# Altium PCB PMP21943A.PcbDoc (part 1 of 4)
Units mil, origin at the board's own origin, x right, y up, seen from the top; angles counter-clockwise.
Board outline 5100 x 3900 mil, 8 copper layers (Top Layer, Signal Layer 1, Signal Layer 2, Signal Layer 3, Signal Layer 4, Signal Layer 5, Signal Layer 6, Bottom Layer), stack 61.6 mil thick; 371 components, 163 nets, 967 pads, 1147 vias.
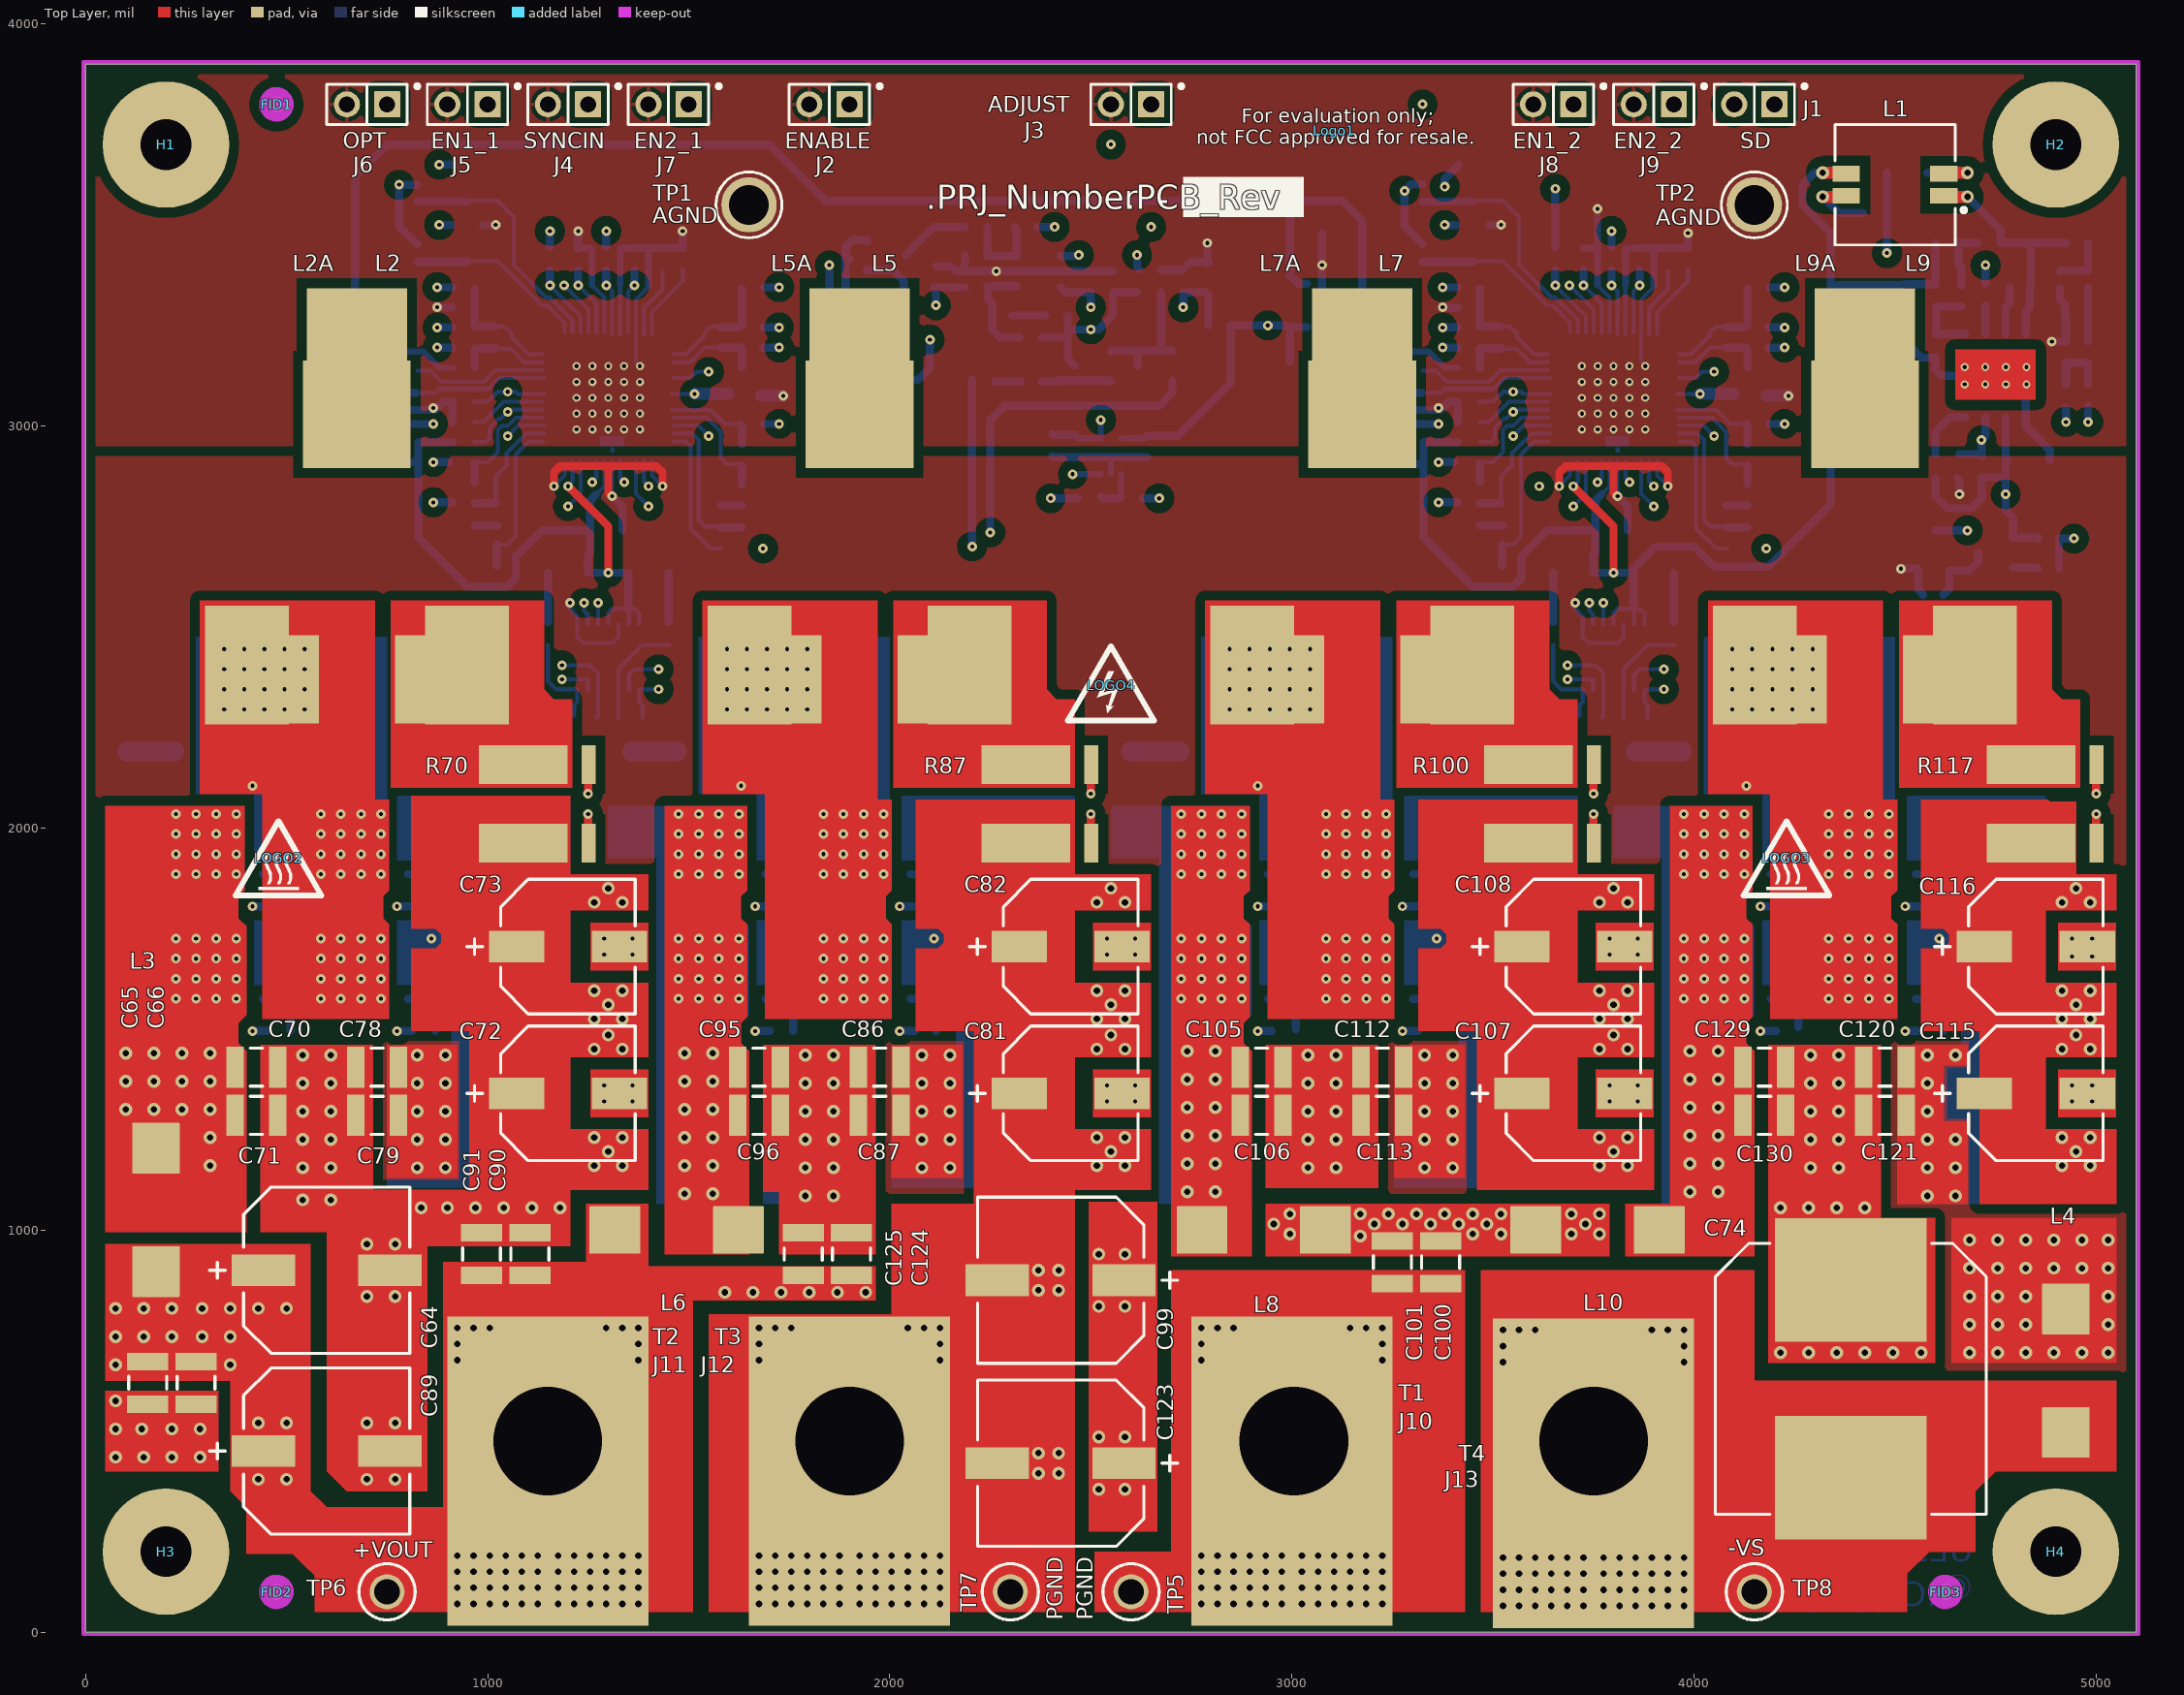
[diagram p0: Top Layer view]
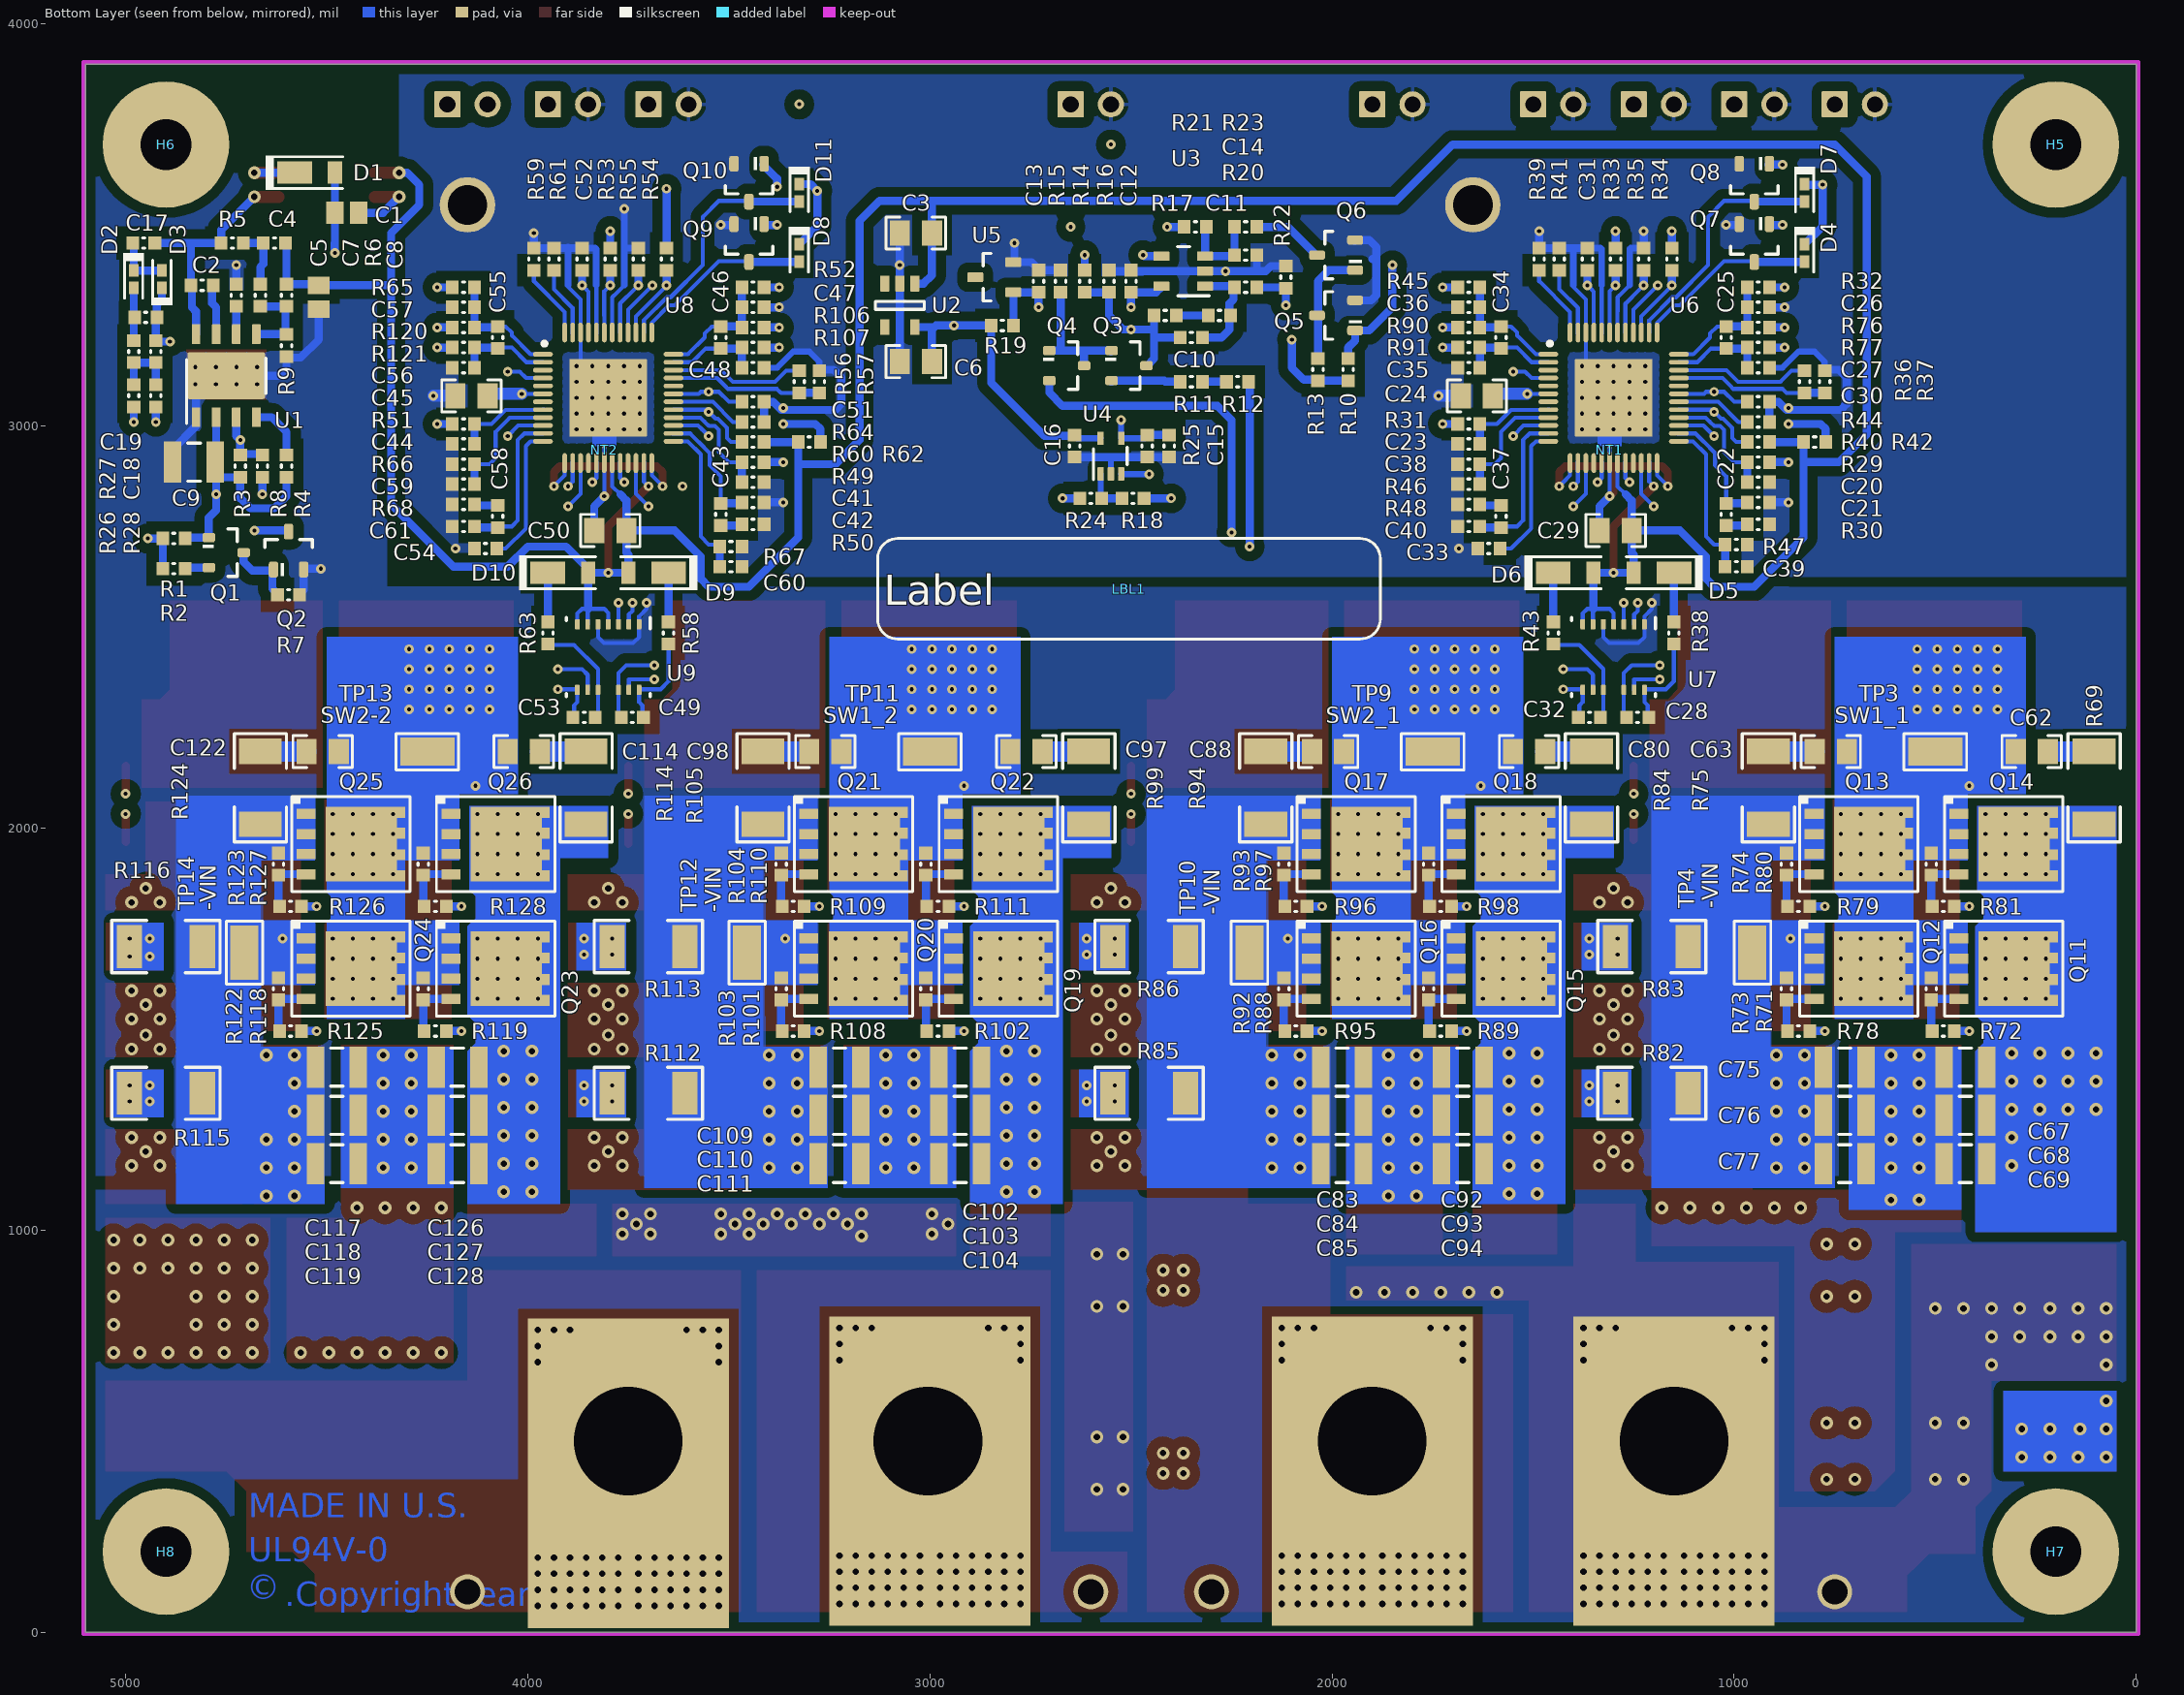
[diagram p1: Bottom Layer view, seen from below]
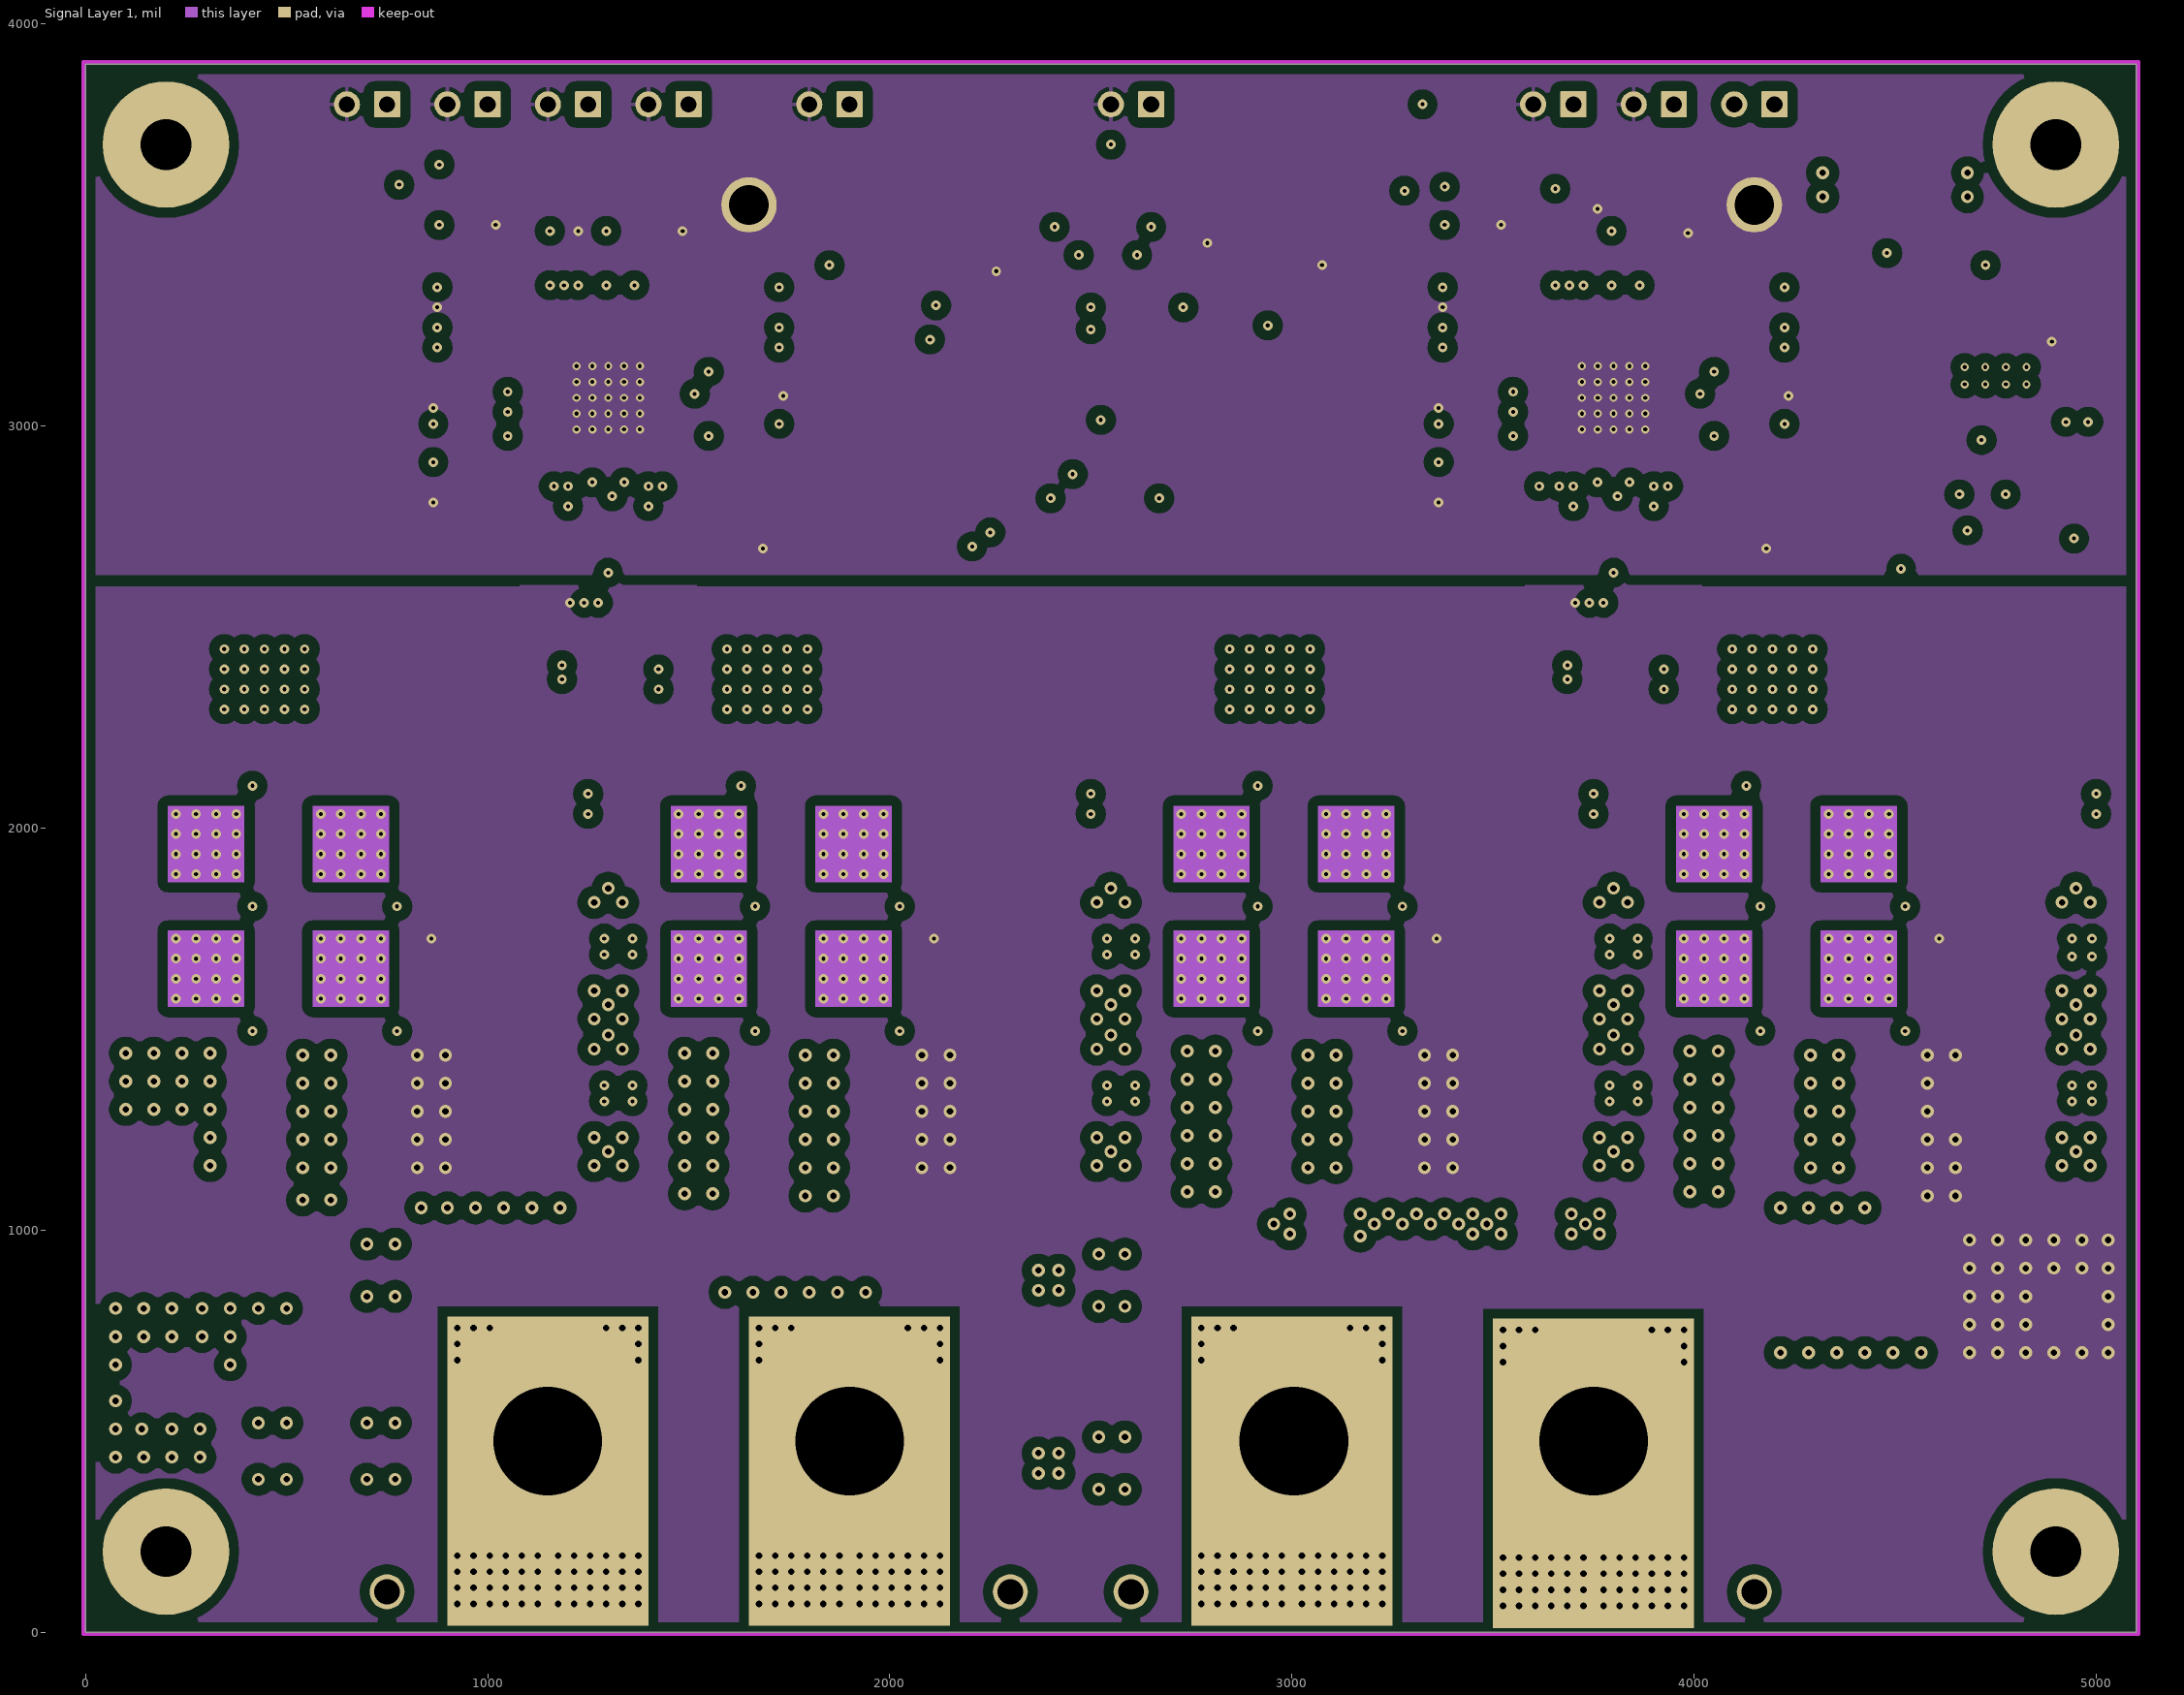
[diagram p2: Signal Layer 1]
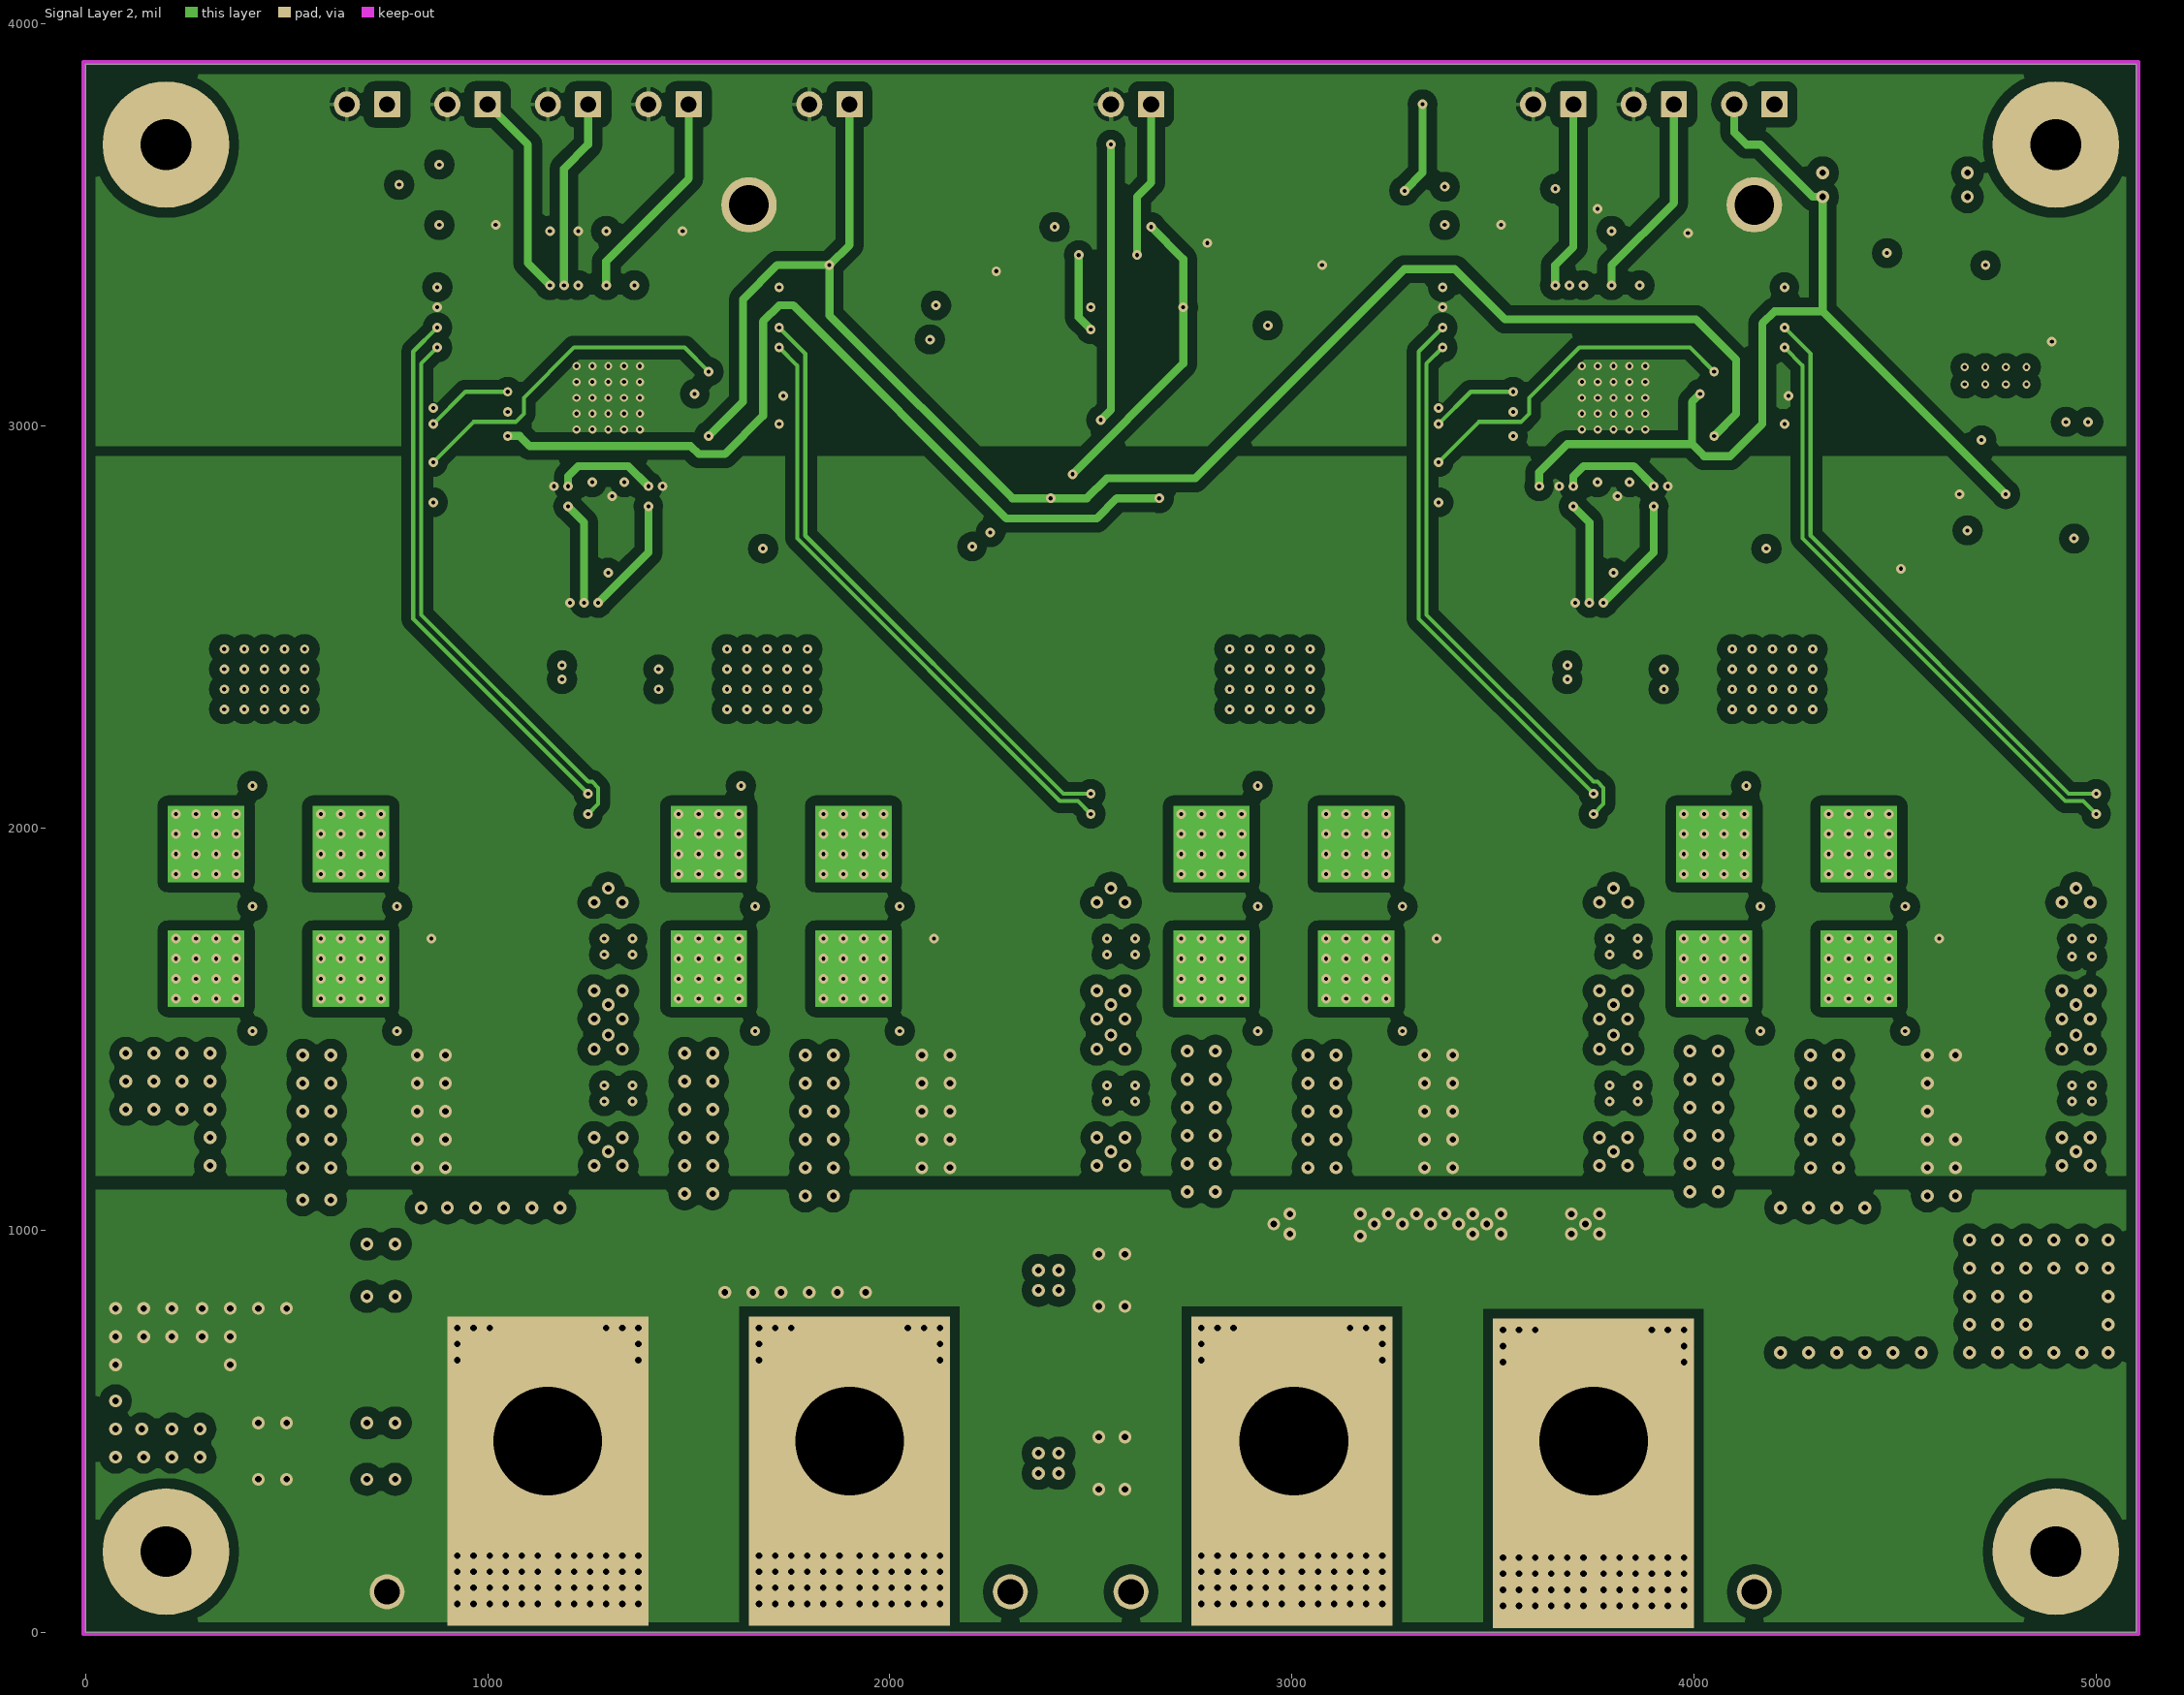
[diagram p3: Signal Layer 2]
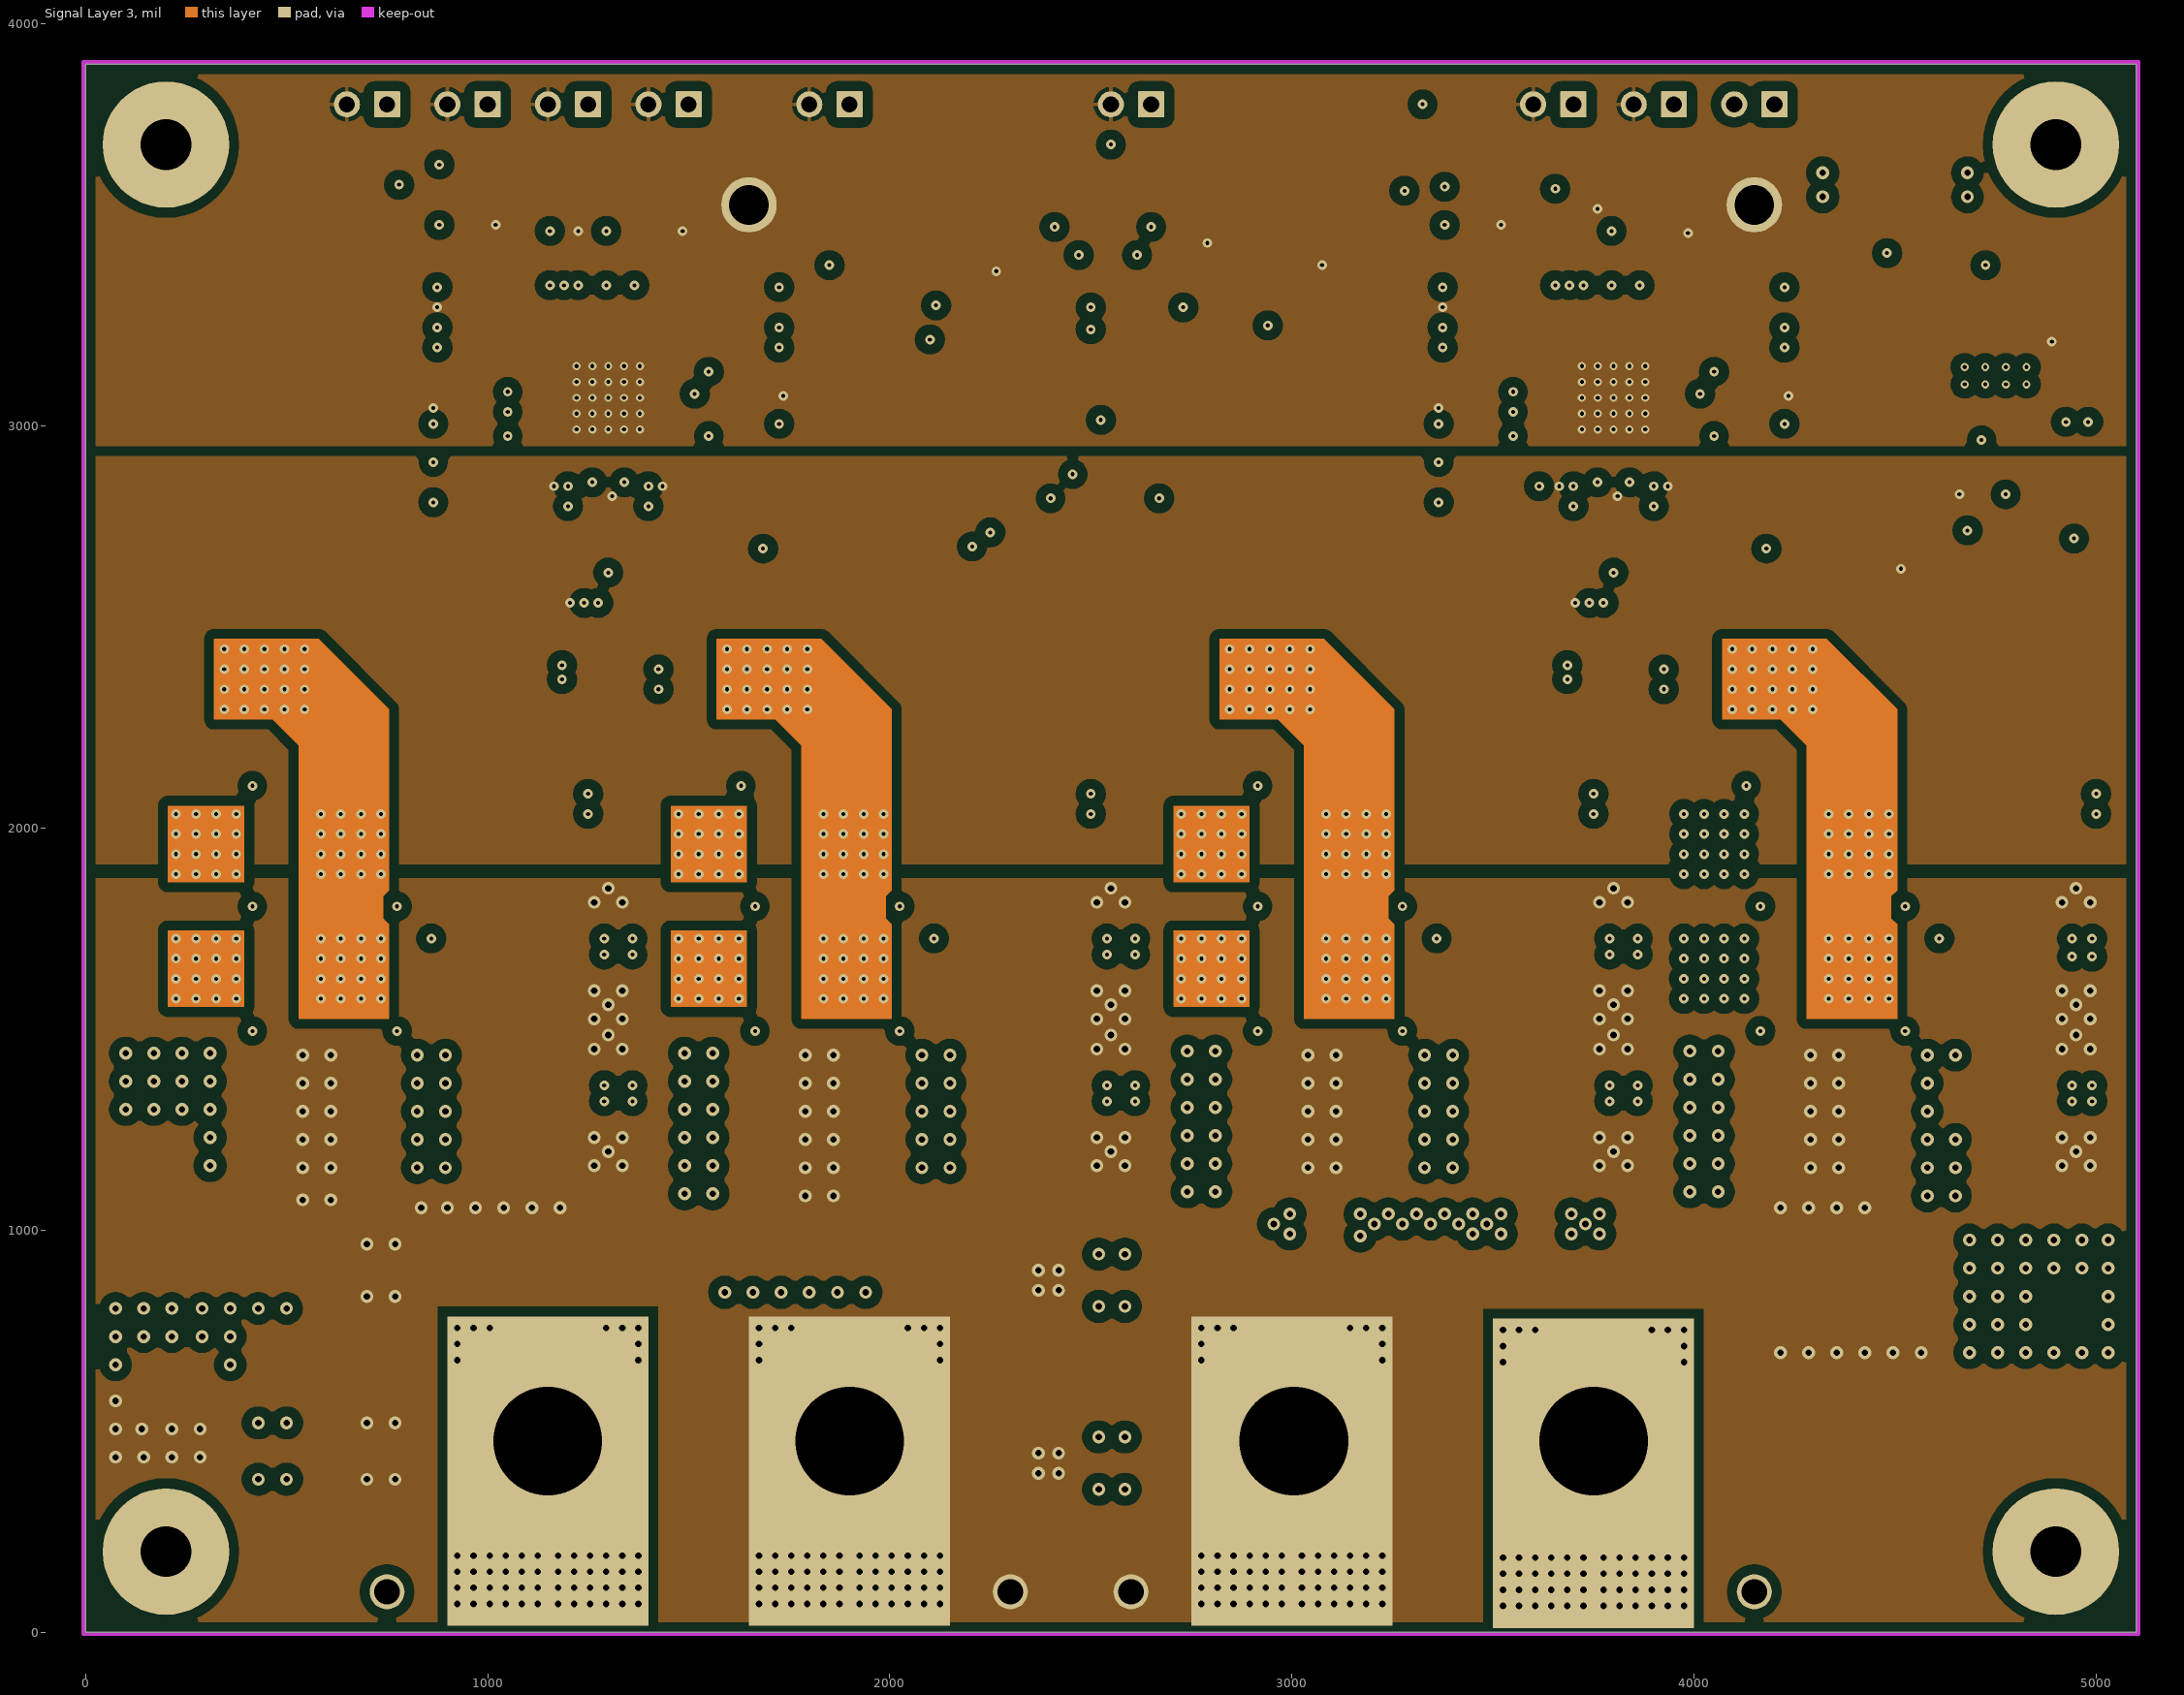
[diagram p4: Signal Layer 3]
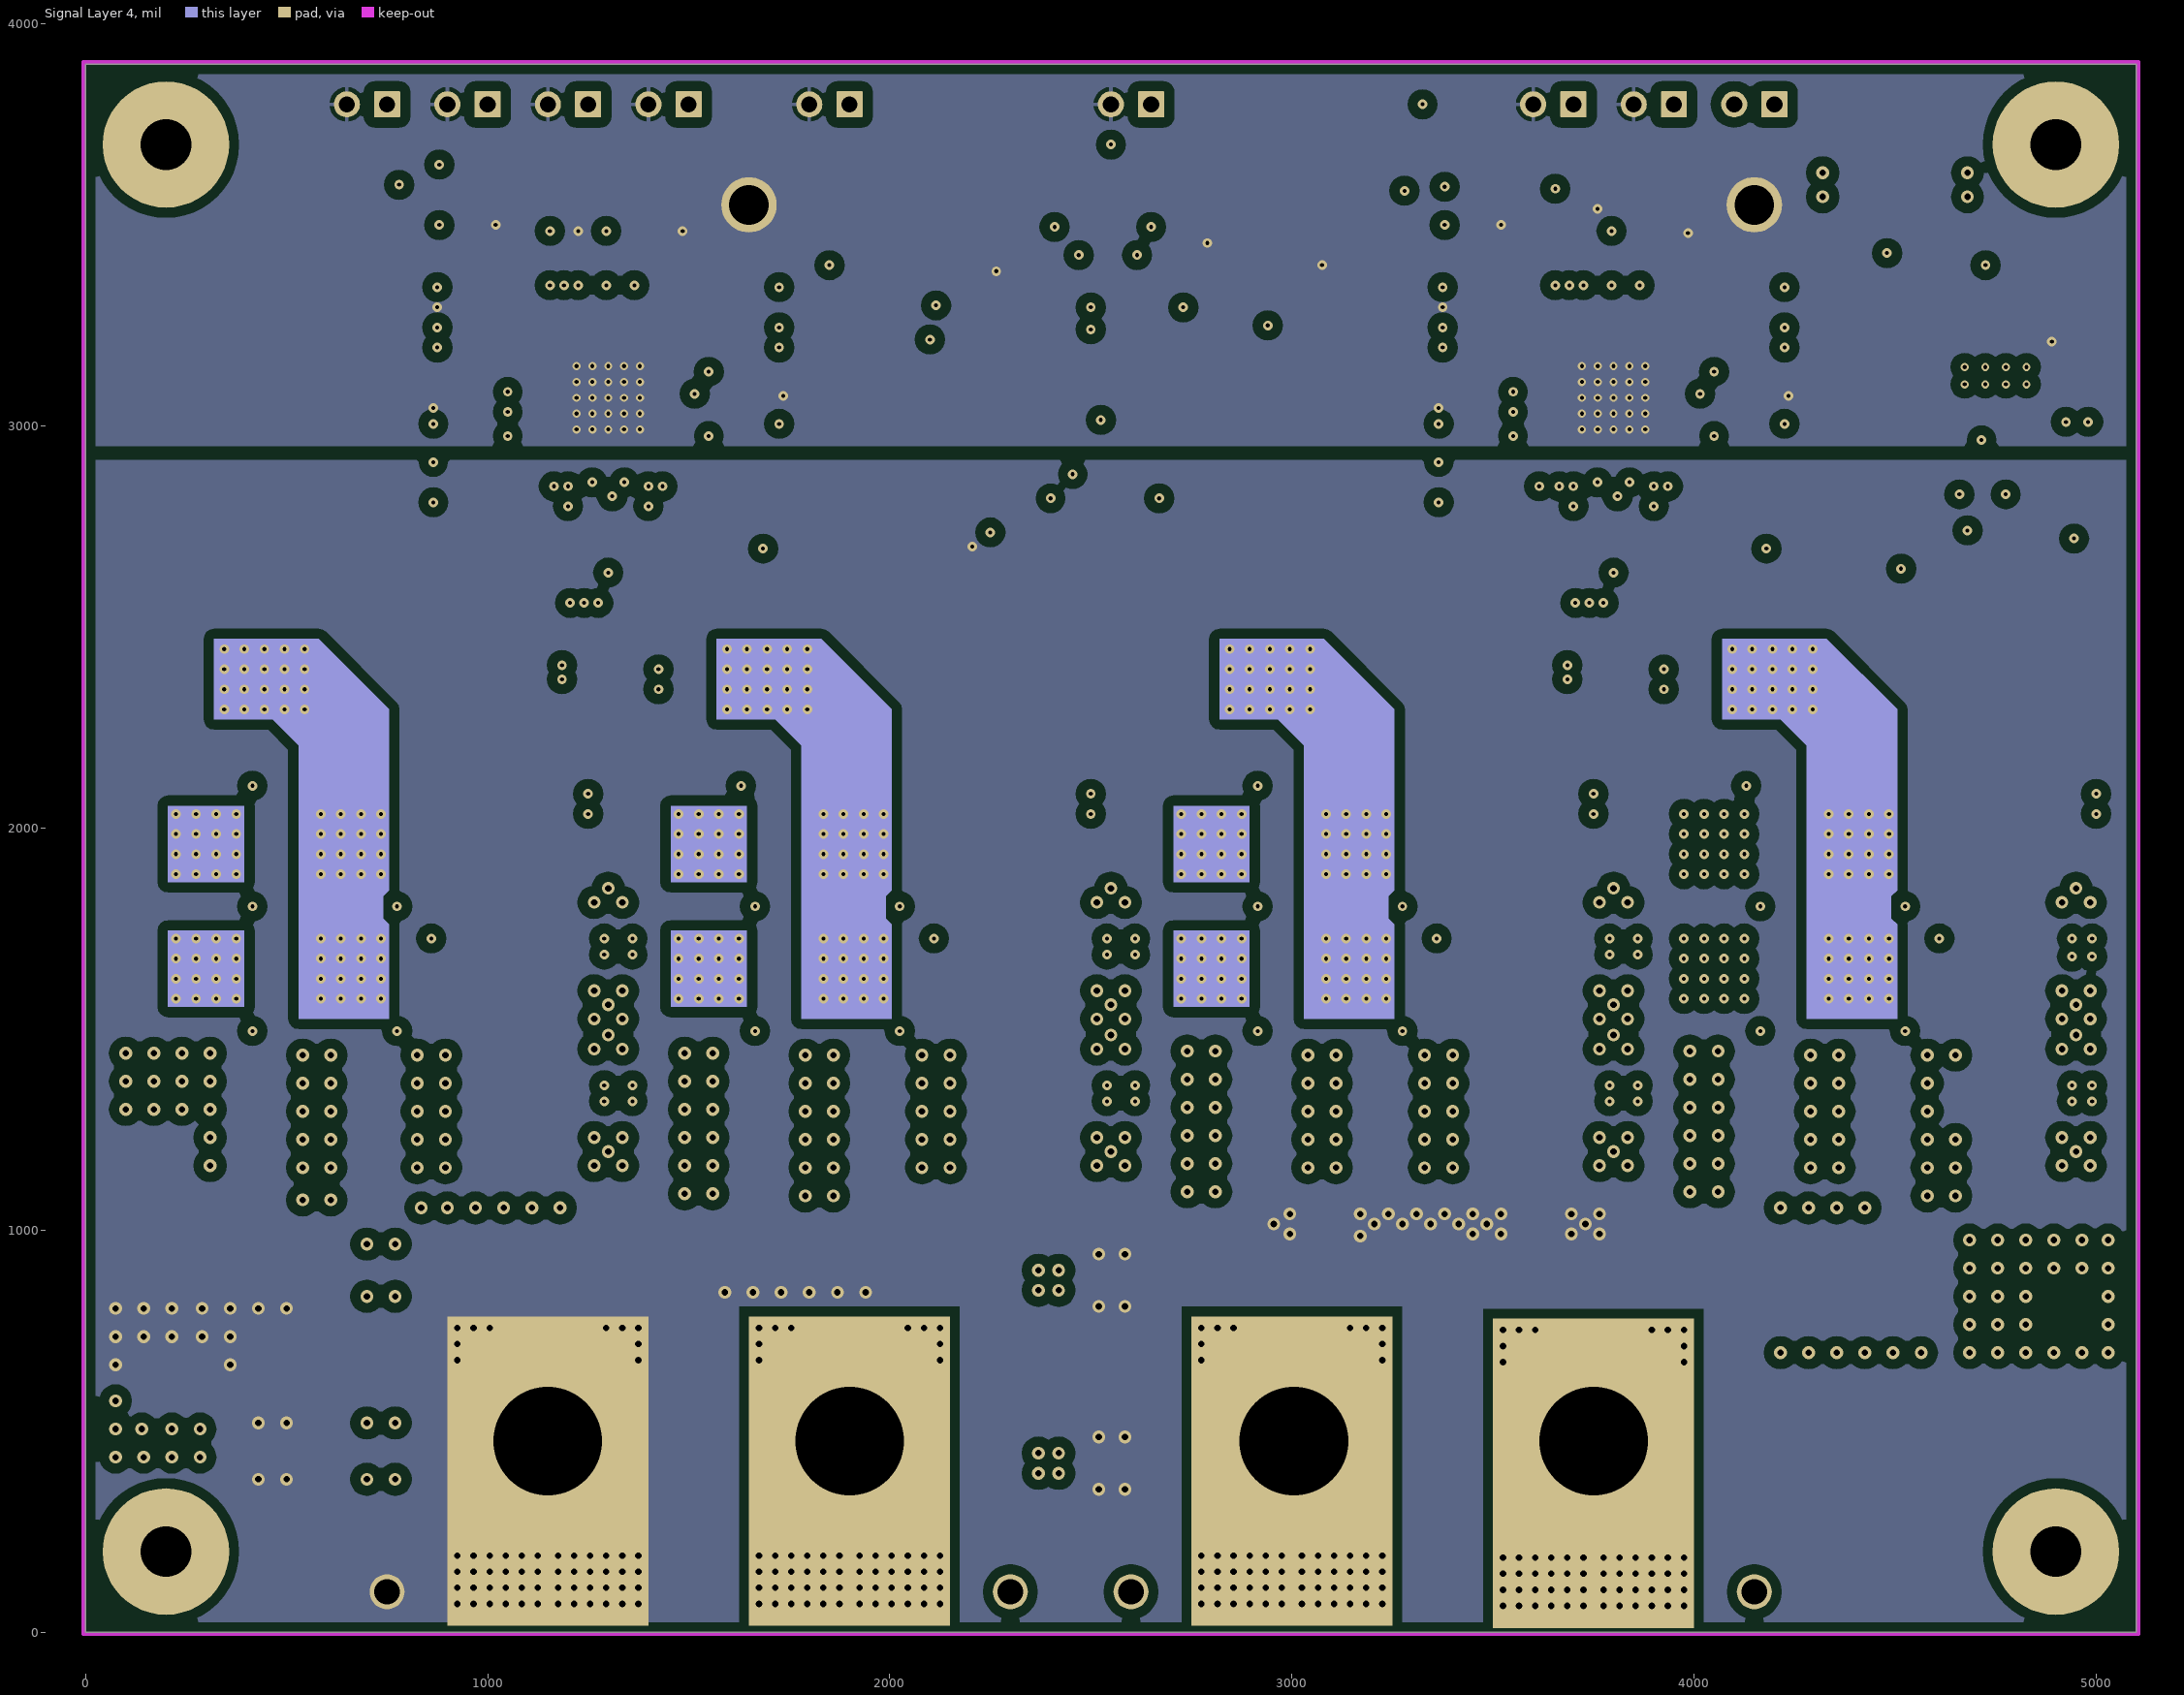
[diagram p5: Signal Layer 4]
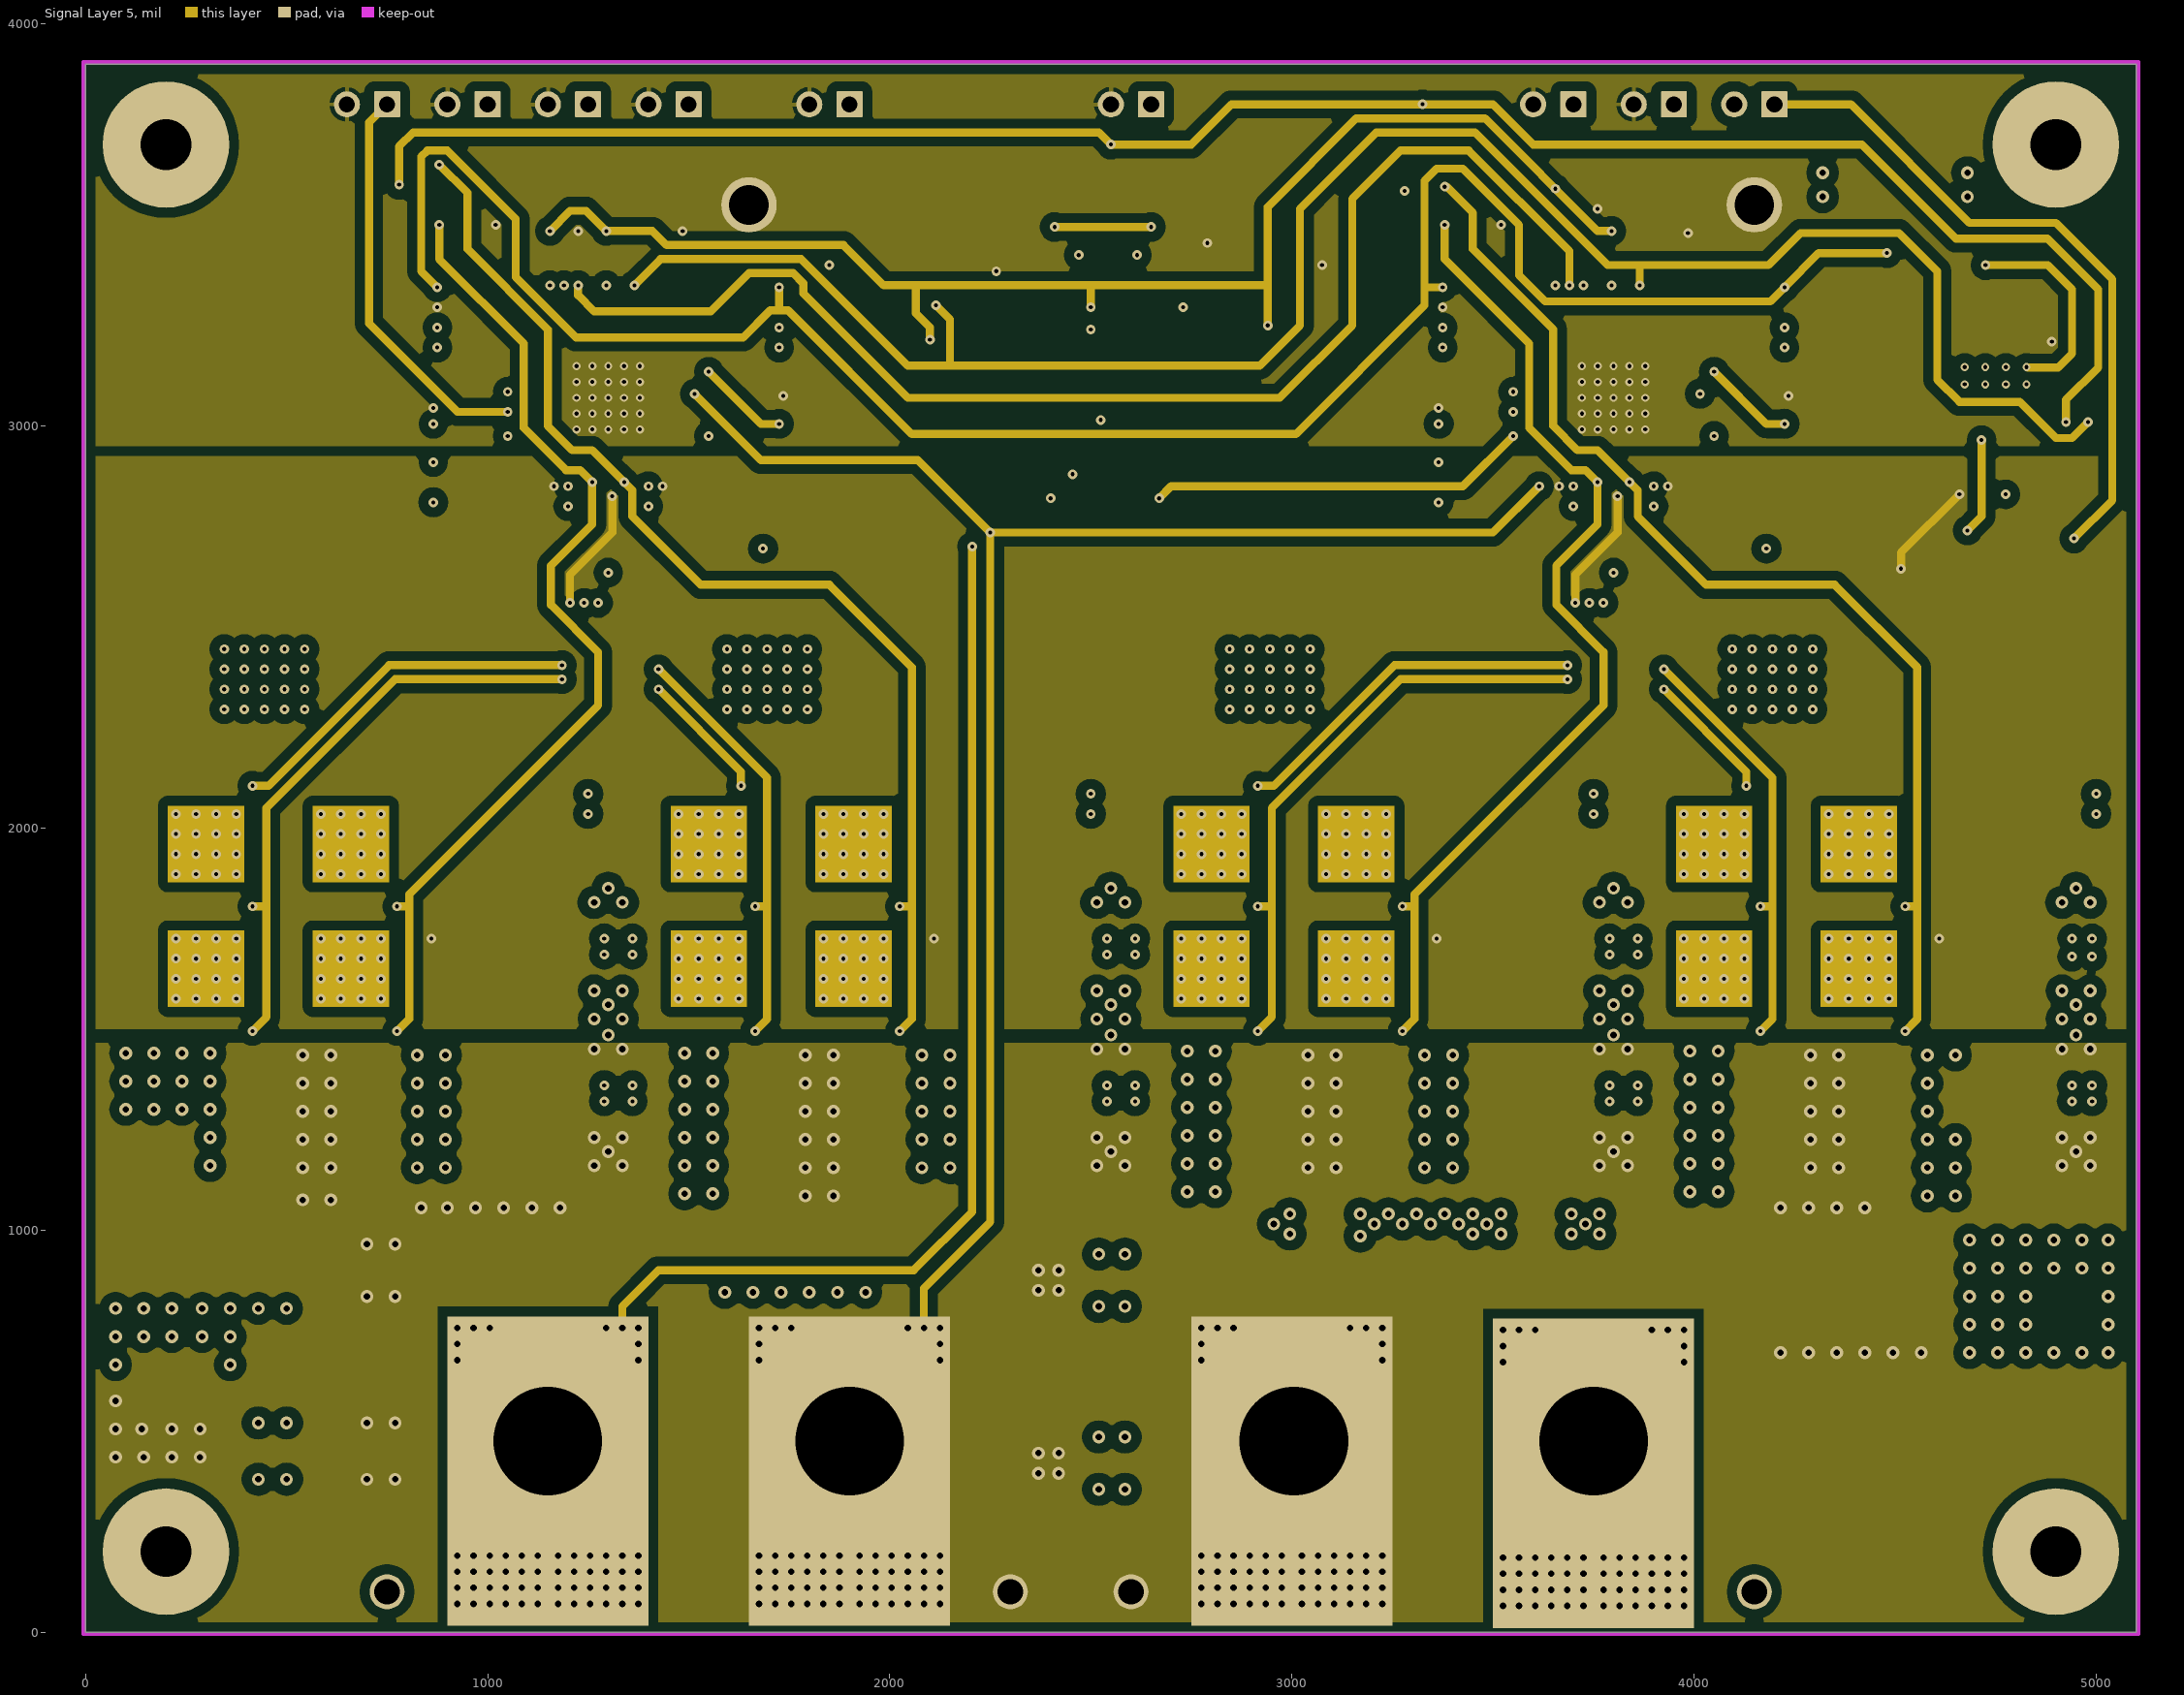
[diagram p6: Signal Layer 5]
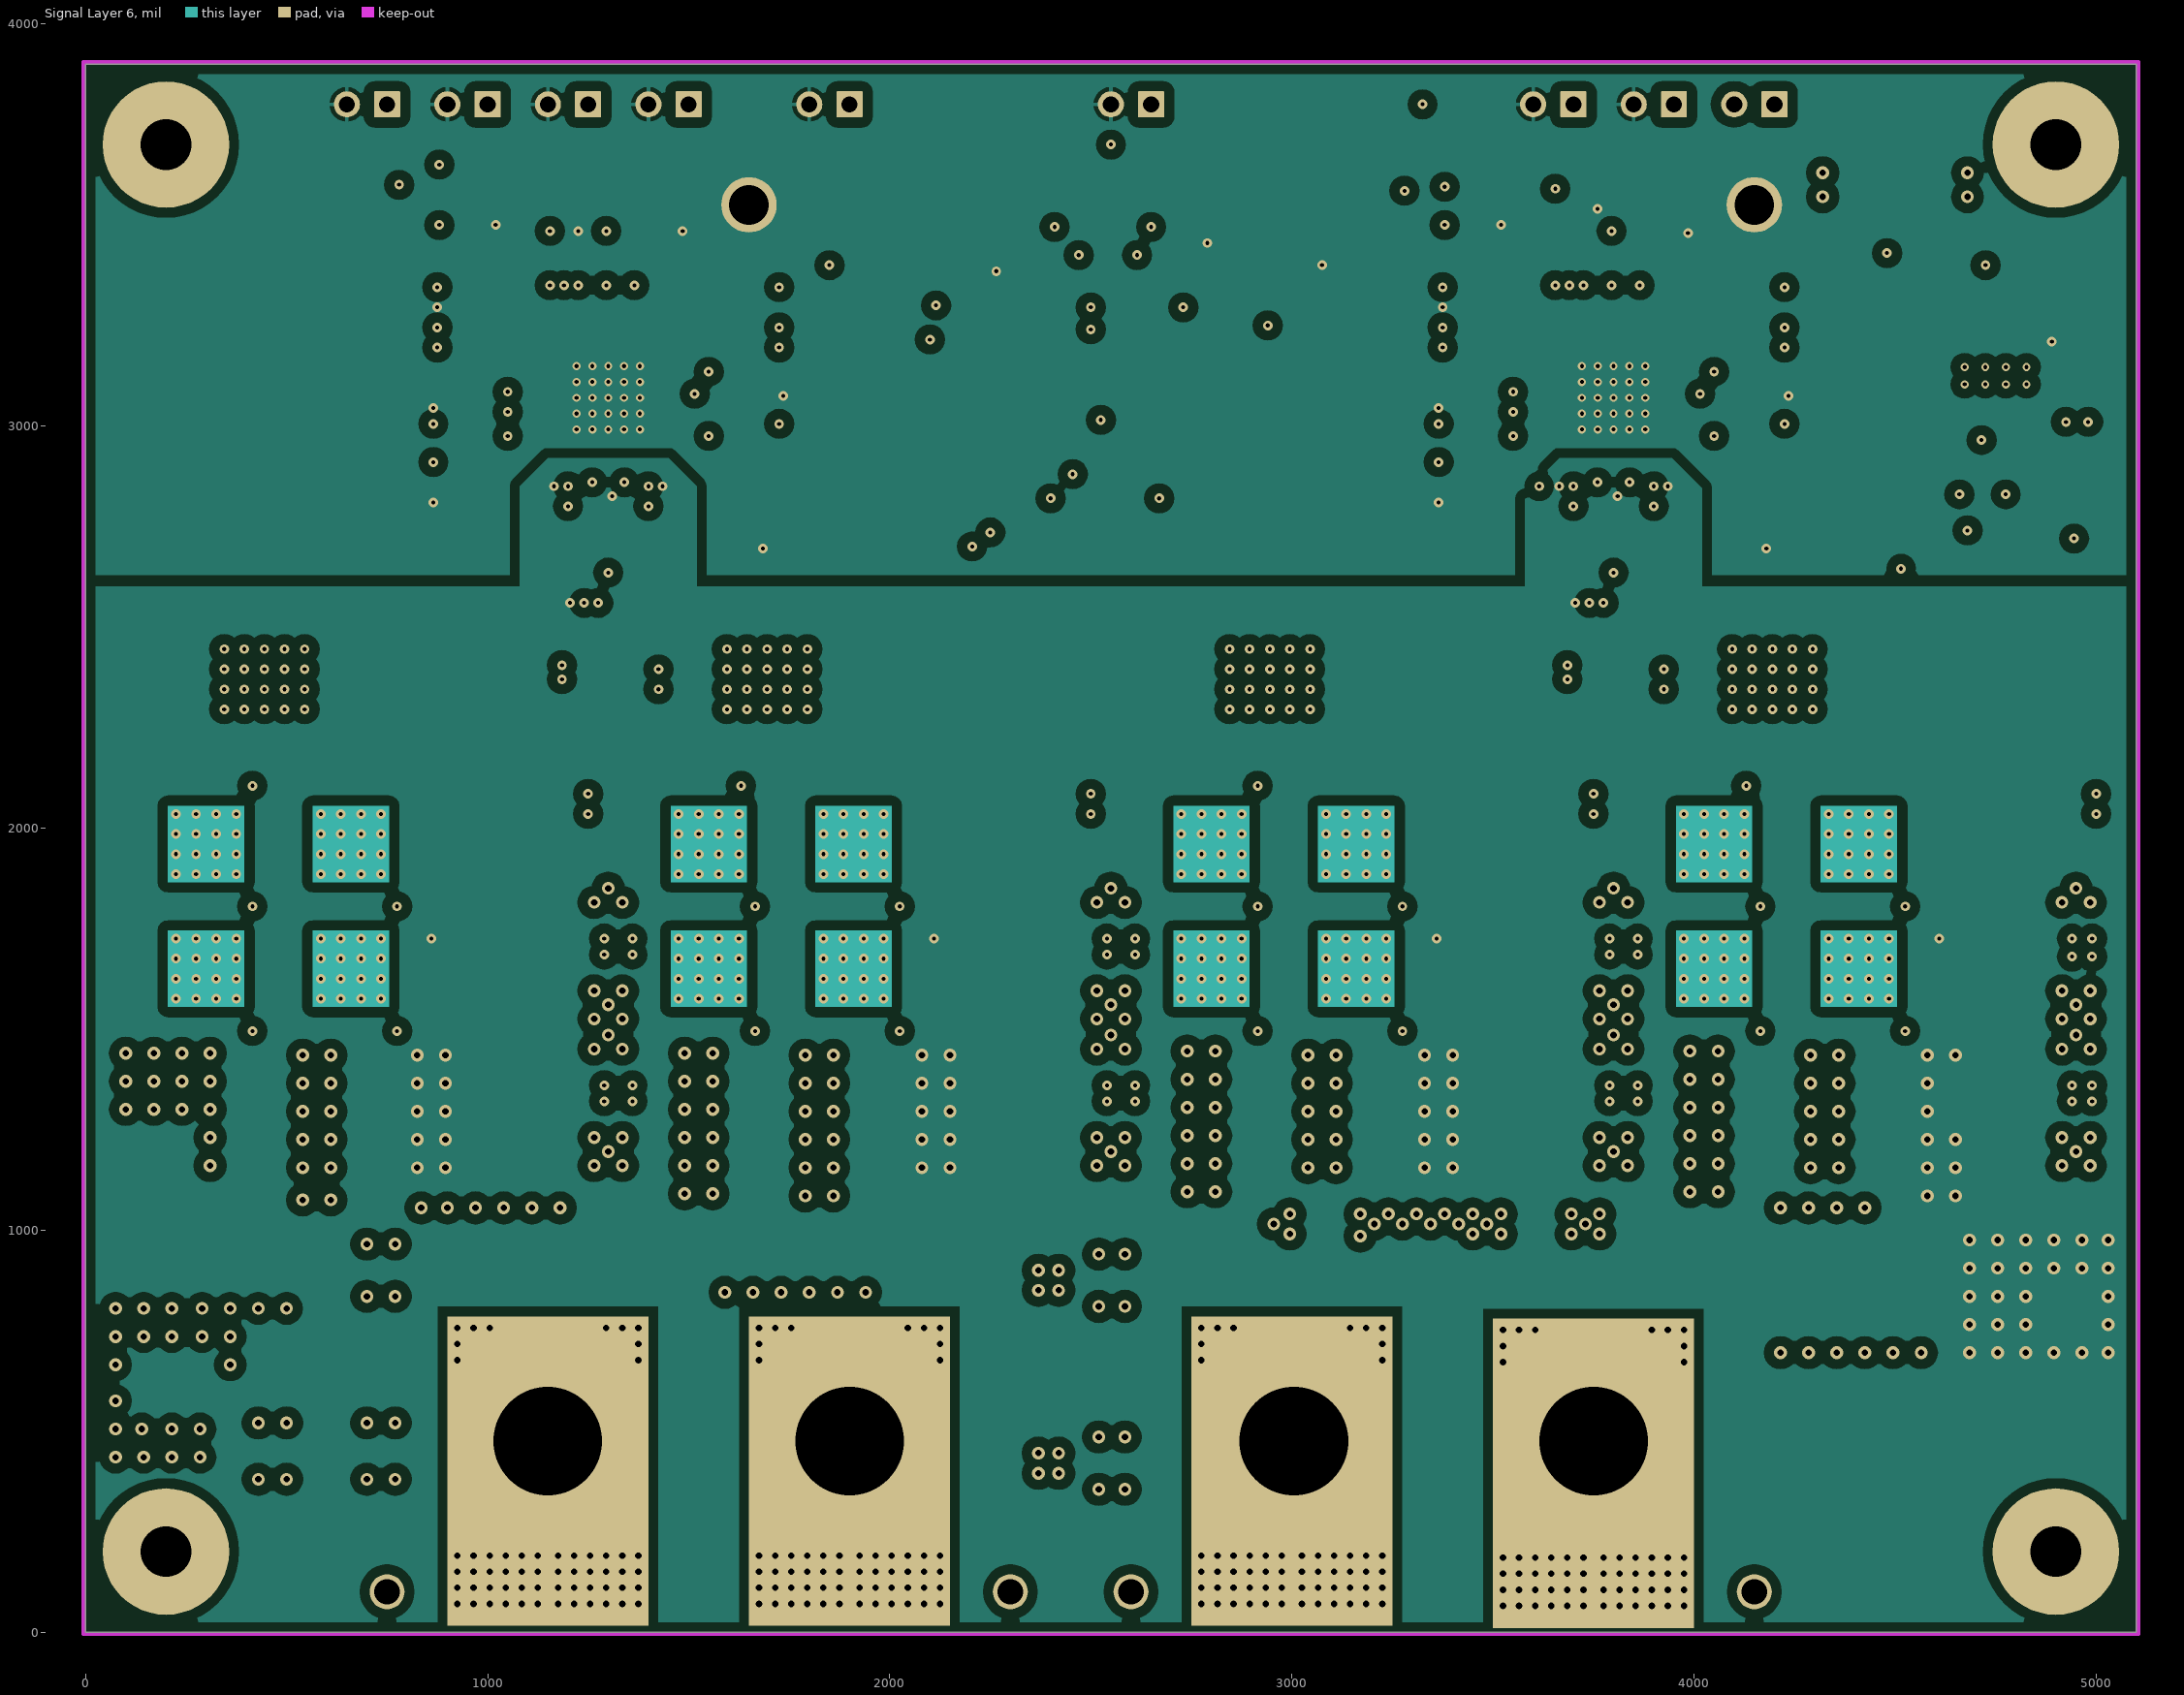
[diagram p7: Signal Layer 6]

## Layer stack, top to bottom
Top Solder: solder mask 0.4, Solder Resist, Dk 3.5
Top Layer: signal copper 2.8
Dielectric1: core 5.6, FR-4, Dk 4.8
Signal Layer 1: signal copper 2.8
Dielectric 2: prepreg 5.6, FR-4, Dk 4.2
Signal Layer 2: signal copper 2.8
Dielectric 3: core 5.6, FR-4, Dk 4.2
Signal Layer 3: signal copper 2.8
Dielectric4: prepreg 5.6, FR-4, Dk 4.2
Signal Layer 4: signal copper 2.8
Dielectric 5: core 5.6, FR-4, Dk 4.2
Signal Layer 5: signal copper 2.8
Dielectric 6: prepreg 5.6, FR-4, Dk 4.2
Signal Layer 6: signal copper 2.8
Dielectric 7: core 5.6, FR-4, Dk 4.8
Bottom Layer: signal copper 2.8
Bottom Solder: solder mask 0.4, Solder Resist, Dk 3.5

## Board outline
0,0 5100,0 5100,3900 0,3900

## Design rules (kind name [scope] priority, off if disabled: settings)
AcuteAngle [All] p1: minimum=4.50000000000000E+0001 checktracksonly=FALSE
AssemblyTestPointUsage [All] p1: valid=2
Clearance Clearance_Lugs2BoardEdge [HasFootprint('Panduit_CXS70-14-C') vs IsKeepOut] p1: gap=0 ignorepadtopadclearanceinfootprint=FALSE
Clearance Clearance_Keepouts [((IsTrack Or IsArc) And Not InPoly) And IsFree and IsKeepOut vs ((IsTrack Or IsArc) And Not InPoly) And IsFree and IsKeepOut] p2: gap=0 ignorepadtopadclearanceinfootprint=FALSE
Clearance Clearance_BoardEdge_MountingHoles [OnCopper and InComponentClass('Mounting Holes') vs IsKeepOut] p3: gap=40 ignorepadtopadclearanceinfootprint=FALSE except(0: Arc-Hole Track-Hole SMDPad-Hole THPad-Hole Via-Hole Fill-Hole Poly-Hole Region-Hole Text-Hole)
Clearance Clearance_BoardEdge_Poly [OnCopper and InPoly vs IsKeepOut] p4: gap=25 ignorepadtopadclearanceinfootprint=FALSE except(0: Arc-Hole Track-Hole SMDPad-Hole THPad-Hole Via-Hole Fill-Hole Poly-Hole Region-Hole Text-Hole)
Clearance Clearance_BoardEdge [OnCopper and Not InComponentClass('Logo') and not InComponentClass('FiducialMark') and not InRegion(1000,500,4000,800) and Not IsKeepout vs IsKeepOut] p5: gap=50 ignorepadtopadclearanceinfootprint=FALSE except(0: Arc-Hole Track-Hole SMDPad-Hole THPad-Hole Via-Hole Fill-Hole Poly-Hole Region-Hole Text-Hole)
Clearance Clearance_Poly [InPolygon] p6: gap=25 ignorepadtopadclearanceinfootprint=FALSE except(0: Arc-Hole Track-Hole SMDPad-Hole THPad-Hole Via-Hole Fill-Hole Poly-Hole Region-Hole Text-Hole)
Clearance [All] p7: gap=7.87 ignorepadtopadclearanceinfootprint=FALSE except(0: Arc-Hole Track-Hole SMDPad-Hole THPad-Hole Via-Hole Fill-Hole Poly-Hole Region-Hole Text-Hole)
ComponentClearance ComponentClearance_Inductors [HasFootprint('FP-7443641500_SMT_IND_28MM0_19MM4-MFG') vs HasFootprint('9R6UH_SMT_IND_22MM')] p1: gap=0 collisioncheckmode=3 verticalgap=0 showdistances=FALSE
ComponentClearance ComponentClearance_NetTie1 [HasFootprint('PHP0048D_L') vs HasFootprint('Net-Tie_10mil')] p2: gap=0 collisioncheckmode=3 verticalgap=0 showdistances=FALSE
ComponentClearance ComponentClearance_NetTie2 [HasFootprint('MXA20A_N') vs HasFootprint('Net-Tie_10mil')] p3: gap=0 collisioncheckmode=3 verticalgap=0 showdistances=FALSE
ComponentClearance ComponentClearance_Lugs2Banana [HasFootprint('Panduit_CXS70-14-C') vs HasFootprint('Johnson_108-0740-001')] p4: gap=0 collisioncheckmode=3 verticalgap=0 showdistances=FALSE
ComponentClearance ComponentClearance_MountingHoles_FiducialMarks [InComponentClass('Mounting Holes') vs InComponentClass('FiducialMark')] p5: gap=50 collisioncheckmode=3 verticalgap=10 showdistances=FALSE
ComponentClearance ComponentClearance_Shunt [InComponentClass('Header') vs InComponentClass('Shunt')] p6: gap=0 collisioncheckmode=3 verticalgap=0 showdistances=FALSE
ComponentClearance ComponentClearance_Logo [InComponentClass('Logo')] p7: gap=50 collisioncheckmode=3 verticalgap=10 showdistances=FALSE
ComponentClearance ComponentClearance_ScrewToNut [(HasFootprint('NY PMS 440 0025 PH')) vs HasFootprint('KEYSTONE_2205')] p8: gap=0 collisioncheckmode=3 verticalgap=0 showdistances=FALSE
ComponentClearance ComponentClearance_MountingHoles [InComponentClass('Mounting Holes')] p9: gap=50 collisioncheckmode=3 verticalgap=100000 showdistances=FALSE
ComponentClearance ComponentClearance_SmallPassives [HasFootprint('0201*') or HasFootprint('0402*') or HasFootprint('0508') or HasFootprint('0603*') or HasFootprint('0612') or HasFootprint('0805*') or HasFootprint('0815*') or HasFootprint('0830*') or HasFootprint('1206*') or HasFootprint('1210*') or HasFootprint('1808*') or HasFootprint('1812*') or HasFootprint('1825*') or HasFootprint('2010*') or HasFootprint('2220*') or HasFootprint('2225*') or HasFootprint('2512*') or HasFootprint('2728*') or HasFootprint('3518*') vs HasFootprint('0201*') or HasFootprint('0402*') or HasFootprint('0508') or HasFootprint('0603*') or HasFootprint('0612') or HasFootprint('0805*') or HasFootprint('0815*') or HasFootprint('0830*') or HasFootprint('1206*') or HasFootprint('1210*') or HasFootprint('1808*') or HasFootprint('1812*') or HasFootprint('1825*') or HasFootprint('2010*') or HasFootprint('2220*') or HasFootprint('2225*') or HasFootprint('2512*') or HasFootprint('2728*') or HasFootprint('3518*')] p10: gap=10 collisioncheckmode=3 verticalgap=10 showdistances=FALSE
ComponentClearance ComponentClearance_THtoSMT [IsThruComponent vs IsSMTComponent] p11: gap=50 collisioncheckmode=3 verticalgap=30 showdistances=FALSE
ComponentClearance ComponentClearance_THtoTH [IsThruComponent vs IsThruComponent] p12: gap=50 collisioncheckmode=3 verticalgap=30 showdistances=FALSE
ComponentClearance [All] p13: gap=30 collisioncheckmode=3 verticalgap=10 showdistances=FALSE
DiffPairsRouting [All] p1: maxlimit=100 minlimit=10 mostfreqgap=10 toplayer_minwidth=15 toplayer_maxwidth=15 toplayer_prefwidth=15 midlayer1_minwidth=15 midlayer1_maxwidth=15 midlayer1_prefwidth=15 midlayer2_minwidth=15 midlayer2_maxwidth=15 midlayer2_prefwidth=15 midlayer3_minwidth=15 midlayer3_maxwidth=15 midlayer3_prefwidth=15 midlayer4_minwidth=15 midlayer4_maxwidth=15 midlayer4_prefwidth=15 midlayer5_minwidth=15 midlayer5_maxwidth=15 midlayer5_prefwidth=15 midlayer6_minwidth=15 midlayer6_maxwidth=15 midlayer6_prefwidth=15 bottomlayer_minwidth=15 bottomlayer_maxwidth=15 bottomlayer_prefwidth=15 maxuncoupledlength=1000
FabricationTestPointUsage TestPointUsage [All] p1: valid=2 allowmultiple=FALSE
FabricationTestpoint Testpoint [All] p1: side=3 testpointundercomponent=TRUE minsize=40 maxsize=100 preferedsize=60 minholesize=0 maxholesize=40 preferedholesize=32 testpointgrid=1 allowsidetop=TRUE allowsidebottom=TRUE usegrid=TRUE gridtolerance=0.01
FanoutControl Fanout_LCC [IsLCC] p1: bgadir=Out bgaviamode=Centered fanoutstyle=Auto fanoutdirection=Alternating viagrid=1 // Fanout_LCC (Default Rule)
FanoutControl Fanout_BGA [IsBGA] p2: bgadir=Out bgaviamode=Centered fanoutstyle=Auto fanoutdirection=Alternating viagrid=1 // Fanout_BGA (Default Rule)
FanoutControl Fanout_Default [All] p4: bgadir=Out bgaviamode=Centered fanoutstyle=Auto fanoutdirection=Alternating viagrid=1 // Fanout_Default (Default Rule)
FanoutControl Fanout_Small [(CompPinCount < 5)] p5: bgadir=Out bgaviamode=Centered fanoutstyle=Auto fanoutdirection=OutThenIn viagrid=1 // Fanout_Small (Default Rule)
Height [All] p1: minheight=0 maxheight=1010 prefheight=500
HoleSize [All] p1: absolutevalues=TRUE maxlimit=500 minlimit=7.87 maxpercent=80.000 minpercent=20.000
HoleToHoleClearance I/OHoleClearance [HasFootprint('Johnson_108-0740-001') vs HasFootprint('Panduit_CXS70-14-C')] p1: gap=0 allowstackedmicrovias=TRUE
HoleToHoleClearance [All] p2: gap=10 allowstackedmicrovias=TRUE
MinimumAnnularRing MinimumAnnularRing_ThermalPadVias [IsVia and InAnyComponent] p1: minimumring=5
MinimumAnnularRing [All] p2: minimumring=7
MinimumSolderMaskSliver MinimumSolderMaskSliver_Logo [InComponentClass('Logo') vs InComponentClass('Logo')] p1: minsoldermaskwidth=0.7
MinimumSolderMaskSliver [All] p2: minsoldermaskwidth=1.9
PlaneConnect [All] p1: planeconnectstyle=Direct reliefexpansion=10 reliefentries=4 reliefconductorwidth=10 reliefairgap=10
PolygonConnect PolygonConnect_AGND [InNet('AGND') vs (HasFootprint('SAMTEC_HMTSW-130-07-G-D-240') OR HasFootprint('Samtec_HTSW-102-07-G-S') OR HasFootprint('Samtec_HTSW-103-07-G-S'))] p1: connectstyle=Relief reliefconductorwidth=10 reliefentries=4 polygonreliefangle="90 Angle" airgapwidth=10
PolygonConnect [All] p2: connectstyle=Direct reliefconductorwidth=10 reliefentries=4 polygonreliefangle="90 Angle" airgapwidth=10
RoutingVias ThermalPadVias [IsVia and InAnyComponent] p1: holewidth=7.87 width=19.68 viastyle="Through Hole" minholewidth=7.87 minwidth=19.68 maxholewidth=16 maxwidth=32
RoutingVias [All] p2: holewidth=16 width=32 viastyle="Through Hole" minholewidth=7.87 minwidth=20 maxholewidth=40 maxwidth=65
SilkToBoardRegionClearance [NOT ((IsComment OR IsDesignator) AND (Hide <> 'FAIL'))AND NOT InRegion (100,-500,8000,1500)] p1:
SilkToSilkClearance SilkToSilkClearance_Pb-FreeLogo [(HasFootprint('Pb-Free_Overlay_Medium') OR HasFootprint('Pb-Free_Overlay_Small')) vs (HasFootprint('Pb-Free_Overlay_Medium') OR HasFootprint('Pb-Free_Overlay_Small'))] p1: silktosilkclearance=0
SilkToSilkClearance [All] p2: silktosilkclearance=5
SilkToSolderMaskClearance "Silk to Solder Mask Opening" [All] p1: minsilkscreentomaskgap=1 clearancetoexposedcopper=FALSE
SolderMaskExpansion [All] p1: expansion=1.97
Width [All] p1: maxlimit=100 minlimit=6 preferedwidth=10 checkconnectedcopper=TRUE
13 further rules are at their usual default settings.

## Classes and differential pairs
component class Header: J1 J2 J3 J4 J5 J6 J7 J8 J9
component class AssemblyNote: ZZ1 ZZ2 ZZ3 ZZ4
component class SH7: FID1 FID2 FID3 H1 H2 H3 H4 H5 H6 H7 H8 LBL1 Logo1 LOGO2 LOGO3 LOGO4 ZZ1 ZZ2 ZZ3 ZZ4
component class FiducialMark: FID1 FID2 FID3
component class Label: LBL1
component class "Mounting Holes": H1 H2 H3 H4
component class SH3: C20 C21 C22 C23 C24 C25 C26 C27 C28 C29 C30 C31 C32 C33 C34 C35 C36 C37 C38 C39 C40 D4 D5 D6 D7 J4 J5 J6 J7 NT1 Q7 Q8 R29 R30 R31 R32 R33 R34 R35 R36 R37 R38 R39 R40 R41 R42 R43 R44 R45 R46 R47 R48 TP1 U6 U7
component class SH5: C62 C63 C64 C65 C66 C67 C68 C69 C70 C71 C72 C73 C74 C75 C76 C77 C78 C79 C80 C81 C82 C83 C84 C85 C86 C87 C88 C89 C90 C91 C92 C93 C94 C95 C96 J10 J11 J12 J13 L2 L3 L4 L5 L6 Q11 Q12 Q13 Q14 Q15 Q16 Q17 Q18 R69 R70 R71 R72 R73 R74 R75 R76 R77 R78 R79 R80 R81 R82 R83 R84 R85 R86 R87 R88 R89 R90 R91 R92 R93 R94 R95 R96 R97 R98 T1 T2 T3 T4 TP3 TP4 TP5 TP6 TP7 TP8 TP9 TP10
component class SH2: C1 C2 C3 C4 C5 C6 C7 C8 C9 C10 C11 C12 C13 C14 C15 C16 C17 C18 C19 D1 D2 D3 J1 J2 J3 L1 Q1 Q2 Q3 Q4 Q5 Q6 R1 R2 R3 R4 R5 R6 R7 R8 R9 R10 R11 R12 R13 R14 R15 R16 R17 R18 R19 R20 R21 R22 R23 R24 R25 R26 R27 R28 U1 U2 U3 U4 U5
component class SH4: C41 C42 C43 C44 C45 C46 C47 C48 C49 C50 C51 C52 C53 C54 C55 C56 C57 C58 C59 C60 C61 D8 D9 D10 D11 J8 J9 NT2 Q9 Q10 R49 R50 R51 R52 R53 R54 R55 R56 R57 R58 R59 R60 R61 R62 R63 R64 R65 R66 R67 R68 TP2 U8 U9 U10
component class SH6: C97 C98 C99 C100 C101 C102 C103 C104 C105 C106 C107 C108 C109 C110 C111 C112 C113 C114 C115 C116 C117 C118 C119 C120 C121 C122 C123 C124 C125 C126 C127 C128 C129 C130 L7 L8 L9 L10 Q19 Q20 Q21 Q22 Q23 Q24 Q25 Q26 R99 R100 R101 R102 R103 R104 R105 R106 R107 R108 R109 R110 R111 R112 R113 R114 R115 R116 R117 R118 R119 R120 R121 R122 R123 R124 R125 R126 R127 R128 TP11 TP12 TP13 TP14

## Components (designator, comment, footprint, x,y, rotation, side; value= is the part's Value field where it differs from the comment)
C1 "Capacitor" 0805L 4450,3530 r180 bottom value=10uF
C2 "Capacitor" 0603L 4810,3350 r0 bottom value=0.01uF
C3 "Capacitor" 0805_HV 3035,3480 r0 bottom value=1uF
C4 "Capacitor" 0603L 4630,3455 r180 bottom value=0.015uF
C5 "Capacitor" 0603L 4725,3325 r90 bottom value=1uF
C6 "Capacitor" 0805_HV 3035,3160 r0 bottom value=2.2uF
C7 "Capacitor" 0603L 4665,3325 r90 bottom value=1000pF
C8 "Capacitor" 0805L 4520,3320 r270 bottom value=10uF
C9 "Capacitor" 1210_180L 4830,2910 r0 bottom value=1uF
C10 "Capacitor" 0603L 2350,3220 r180 bottom value=100pF
C11 "Capacitor" 0603L 2280,3275 r0 bottom value=0.01uF
C12 "Capacitor" 0603L 2500,3360 r90 bottom value=0.1uF
C13 "Capacitor" 0603L 2730,3360 r90 bottom value=1000pF
C14 "Capacitor" 0603L 2215,3425 r180 bottom value=0.01uF
C15 "Capacitor" 0603L 2405,2950 r270 bottom value=0.047uF
C16 "Capacitor" 0603L 2640,2950 r90 bottom value=0.1uF
C17 "Capacitor" 0603L 4955,3455 r0 bottom value=22pF
C18 "Capacitor" 0603L 4925,3185 r90 bottom value=1000pF
C19 "Capacitor" 0603L 4950,3270 r180 bottom value=1000pF
C20 "Capacitor" 0603L 940,2860 r180 bottom value=1000pF
C21 "Capacitor" 0603L 940,2810 r0 bottom value=100pF
C22 "Capacitor" 0603L 1020,2780 r90 bottom value=0.01uF
C23 "Capacitor" 0603L 1660,2955 r0 bottom value=1000pF
C24 "Capacitor" 0805_HV 1640,3075 r0 bottom value=1uF
C25 "Capacitor" 0603L 1020,3220 r270 bottom value=0.22uF
C26 "Capacitor" 0603L 940,3295 r180 bottom value=100pF
C27 "Capacitor" 0603L 940,3145 r180 bottom value=100pF
C28 "Capacitor" 0603L 1240,2275 r180 bottom value=0.22uF
C29 "Capacitor" 0805_HV 1295,2740 r0 bottom value=2.2uF
C30 "Capacitor" 0603L 940,3060 r180 bottom value=1uF
C31 "Capacitor" 0603L 1365,3415 r90 bottom value=100pF
C32 "Capacitor" 0603L 1360,2275 r0 bottom value=0.22uF
C33 "Capacitor" 0603L 1610,2695 r0 bottom value=0.01uF
C34 "Capacitor" 0603L 1580,3220 r90 bottom value=0.22uF
C35 "Capacitor" 0603L 1660,3145 r0 bottom value=100pF
C36 "Capacitor" 0603L 1660,3295 r0 bottom value=100pF
C37 "Capacitor" 0603L 1580,2775 r90 bottom value=0.01uF
C38 "Capacitor" 0603L 1660,2905 r0 bottom value=100pF
C39 "Capacitor" 0603L 995,2650 r180 bottom value=100pF
C40 "Capacitor" 0603L 1660,2750 r0 bottom value=100pF
C41 "Capacitor" 0603L 3440,2860 r180 bottom value=1000pF
C42 "Capacitor" 0603L 3440,2810 r0 bottom value=100pF
C43 "Capacitor" 0603L 3520,2780 r90 bottom value=0.01uF
C44 "Capacitor" 0603L 4160,2955 r0 bottom value=1000pF
C45 "Capacitor" 0805_HV 4140,3075 r0 bottom value=1uF
C46 "Capacitor" 0603L 3520,3220 r270 bottom value=0.22uF
C47 "Capacitor" 0603L 3440,3295 r180 bottom value=100pF
C48 "Capacitor" 0603L 3440,3145 r180 bottom value=100pF
C49 "Capacitor" 0603L 3740,2275 r180 bottom value=0.22uF
C50 "Capacitor" 0805_HV 3795,2740 r0 bottom value=2.2uF
C51 "Capacitor" 0603L 3440,3060 r180 bottom value=1uF
C52 "Capacitor" 0603L 3865,3415 r90 bottom value=100pF
C53 "Capacitor" 0603L 3860,2275 r0 bottom value=0.22uF
C54 "Capacitor" 0603L 4105,2695 r0 bottom value=0.01uF
C55 "Capacitor" 0603L 4075,3220 r90 bottom value=0.22uF
C56 "Capacitor" 0603L 4160,3145 r0 bottom value=100pF
C57 "Capacitor" 0603L 4160,3295 r0 bottom value=100pF
C58 "Capacitor" 0603L 4075,2775 r90 bottom value=0.01uF
C59 "Capacitor" 0603L 4160,2855 r0 bottom value=100pF
C60 "Capacitor" 0603L 3495,2650 r180 bottom value=100pF
C61 "Capacitor" 0603L 4160,2750 r0 bottom value=100pF
C62 "Capacitor" 0805_HV 260,2190 r180 bottom value=100pF
C63 "Capacitor" 0805_HV 760,2190 r0 bottom value=100pF
C64 "Cap_Polarized" CR_1000x1270 600,900 r0 top value=100uF
C65 "GCM32DC72A475KE02L" 1210_220L 155,620 r270 top value=4.7uF
C66 "GCM32DC72A475KE02L" 1210_220L 275,620 r270 top value=4.7uF
C67 "GCM32DC72A475KE02L" 1210_220L 425,1405 r0 bottom value=4.7uF
C68 "GCM32DC72A475KE02L" 1210_220L 425,1285 r0 bottom value=4.7uF
C69 "GCM32DC72A475KE02L" 1210_220L 425,1165 r0 bottom value=4.7uF
C70 "GCM32DC72A475KE02L" 1210_220L 425,1405 r0 top value=4.7uF
C71 "GCM32DC72A475KE02L" 1210_220L 425,1285 r0 top value=4.7uF
C72 "Cap_Polarized" CR_800x1200 1200,1340 r0 top value=39uF
C73 "Cap_Polarized" CR_800x1200 1200,1705 r0 top value=39uF
C74 "Cap_Polarized" CAPSMT_62_LH0 4390,630 r270 top value=100uF
C75 "GCM32DC72A475KE02L" 1210_220L 725,1405 r0 bottom value=4.7uF
C76 "GCM32DC72A475KE02L" 1210_220L 725,1285 r0 bottom value=4.7uF
C77 "GCM32DC72A475KE02L" 1210_220L 725,1165 r0 bottom value=4.7uF
C78 "GCM32DC72A475KE02L" 1210_220L 725,1405 r0 top value=4.7uF
C79 "GCM32DC72A475KE02L" 1210_220L 725,1285 r0 top value=4.7uF
C80 "Capacitor" 0805_HV 1510,2190 r180 bottom value=100pF
C81 "Cap_Polarized" CR_800x1200 2450,1340 r0 top value=39uF
C82 "Cap_Polarized" CR_800x1200 2450,1705 r0 top value=39uF
C83 "GCM32DC72A475KE02L" 1210_220L 1975,1405 r0 bottom value=4.7uF
C84 "GCM32DC72A475KE02L" 1210_220L 1975,1285 r0 bottom value=4.7uF
C85 "GCM32DC72A475KE02L" 1210_220L 1975,1165 r0 bottom value=4.7uF
C86 "GCM32DC72A475KE02L" 1210_220L 1975,1405 r0 top value=4.7uF
C87 "GCM32DC72A475KE02L" 1210_220L 1975,1285 r0 top value=4.7uF
C88 "Capacitor" 0805_HV 2010,2190 r0 bottom value=100pF
C89 "Cap_Polarized" CR_1000x1270 600,450 r0 top value=100uF
C90 "GCM32DC72A475KE02L" 1210_220L 1105,940 r90 top value=4.7uF
C91 "GCM32DC72A475KE02L" 1210_220L 985,940 r90 top value=4.7uF
C92 "GCM32DC72A475KE02L" 1210_220L 1675,1405 r0 bottom value=4.7uF
C93 "GCM32DC72A475KE02L" 1210_220L 1675,1285 r0 bottom value=4.7uF
C94 "GCM32DC72A475KE02L" 1210_220L 1675,1165 r0 bottom value=4.7uF
C95 "GCM32DC72A475KE02L" 1210_220L 1675,1405 r0 top value=4.7uF
C96 "GCM32DC72A475KE02L" 1210_220L 1675,1285 r0 top value=4.7uF
C97 "Capacitor" 0805_HV 2760,2190 r180 bottom value=100pF
C98 "Capacitor" 0805_HV 3260,2190 r0 bottom value=100pF
C99 "Cap_Polarized" CR_1000x1270 2425,875 r180 top value=100uF
C100 "GCM32DC72A475KE02L" 1210_220L 3370,920 r270 top value=4.7uF
C101 "GCM32DC72A475KE02L" 1210_220L 3250,920 r270 top value=4.7uF
C102 "GCM32DC72A475KE02L" 1210_220L 2925,1405 r0 bottom value=4.7uF
C103 "GCM32DC72A475KE02L" 1210_220L 2925,1285 r0 bottom value=4.7uF
C104 "GCM32DC72A475KE02L" 1210_220L 2925,1165 r0 bottom value=4.7uF
C105 "GCM32DC72A475KE02L" 1210_220L 2925,1405 r0 top value=4.7uF
C106 "GCM32DC72A475KE02L" 1210_220L 2925,1285 r0 top value=4.7uF
C107 "Cap_Polarized" CR_800x1200 3700,1340 r0 top value=39uF
C108 "Cap_Polarized" CR_800x1200 3700,1705 r0 top value=39uF
C109 "GCM32DC72A475KE02L" 1210_220L 3225,1405 r0 bottom value=4.7uF
C110 "GCM32DC72A475KE02L" 1210_220L 3225,1285 r0 bottom value=4.7uF
C111 "GCM32DC72A475KE02L" 1210_220L 3225,1165 r0 bottom value=4.7uF
C112 "GCM32DC72A475KE02L" 1210_220L 3225,1405 r0 top value=4.7uF
C113 "GCM32DC72A475KE02L" 1210_220L 3225,1285 r0 top value=4.7uF
C114 "Capacitor" 0805_HV 4010,2190 r180 bottom value=100pF
C115 "Cap_Polarized" CR_800x1200 4850,1340 r0 top value=39uF
C116 "Cap_Polarized" CR_800x1200 4850,1705 r0 top value=39uF
C117 "GCM32DC72A475KE02L" 1210_220L 4475,1405 r0 bottom value=4.7uF
C118 "GCM32DC72A475KE02L" 1210_220L 4475,1285 r0 bottom value=4.7uF
C119 "GCM32DC72A475KE02L" 1210_220L 4475,1165 r0 bottom value=4.7uF
C120 "GCM32DC72A475KE02L" 1210_220L 4475,1405 r0 top value=4.7uF
C121 "GCM32DC72A475KE02L" 1210_220L 4475,1285 r0 top value=4.7uF
C122 "Capacitor" 0805_HV 4510,2190 r0 bottom value=100pF
C123 "Cap_Polarized" CR_1000x1270 2425,420 r180 top value=100uF
C124 "GCM32DC72A475KE02L" 1210_220L 1905,940 r90 top value=4.7uF
C125 "GCM32DC72A475KE02L" 1210_220L 1785,940 r90 top value=4.7uF
C126 "GCM32DC72A475KE02L" 1210_220L 4175,1405 r0 bottom value=4.7uF
C127 "GCM32DC72A475KE02L" 1210_220L 4175,1285 r0 bottom value=4.7uF
C128 "GCM32DC72A475KE02L" 1210_220L 4175,1165 r0 bottom value=4.7uF
C129 "GCM32DC72A475KE02L" 1210_220L 4175,1405 r0 top value=4.7uF
C130 "GCM32DC72A475KE02L" 1210_220L 4175,1285 r0 top value=4.7uF
D1 "DFLS1150-7" PowerDI123 4530,3630 r180 bottom value=150V
D2 "1N4148X-TP" SOD-523 4980,3365 r270 bottom value=75V
D3 "1N4148X-TP" SOD-523 4910,3365 r90 bottom value=75V
D4 "1N4148X-TP" SOD-523 825,3430 r270 bottom value=75V
D5 "DFLS1150-7" PowerDI123 1200,2635 r0 bottom value=150V
D6 "DFLS1150-7" PowerDI123 1400,2635 r180 bottom value=150V
D7 "1N4148X-TP" SOD-523 825,3580 r270 bottom value=75V
D8 "1N4148X-TP" SOD-523 3325,3430 r270 bottom value=75V
D9 "DFLS1150-7" PowerDI123 3700,2635 r0 bottom value=150V
D10 "DFLS1150-7" PowerDI123 3900,2635 r180 bottom value=150V
D11 "1N4148X-TP" SOD-523 3325,3580 r270 bottom value=75V
FID1 "Fiducial" Fiducial10-20 475,3800 r0 top
FID2 "Fiducial" Fiducial10-20 475,100 r0 top
FID3 "Fiducial" Fiducial10-20 4625,100 r0 top
H1 "NY PMS 440 0025 PH" "NY PMS 440 0025 PH" 200,3700 r0 top locked
H2 "NY PMS 440 0025 PH" "NY PMS 440 0025 PH" 4900,3700 r0 top locked
H3 "NY PMS 440 0025 PH" "NY PMS 440 0025 PH" 200,200 r0 top locked
H4 "NY PMS 440 0025 PH" "NY PMS 440 0025 PH" 4900,200 r0 top
H5 "Nut" KEYSTONE_2205 200,3700 r180 bottom locked
H6 "Nut" KEYSTONE_2205 4900,3700 r180 bottom locked
H7 "Nut" KEYSTONE_2205 200,200 r180 bottom locked
H8 "Nut" KEYSTONE_2205 4900,200 r180 bottom locked
J1 "SD" Samtec_HTSW-102-07-G-S 4150,3800 r180 top
J2 "ENABLE" Samtec_HTSW-102-07-G-S 1850,3800 r180 top
J3 "ADJUST" Samtec_HTSW-102-07-G-S 2600,3800 r180 top
J4 "SYNCIN" Samtec_HTSW-102-07-G-S 1200,3800 r180 top
J5 "EN1_1" Samtec_HTSW-102-07-G-S 950,3800 r180 top
J6 "OPT" Samtec_HTSW-102-07-G-S 700,3800 r180 top
J7 "EN2_1" Samtec_HTSW-102-07-G-S 1450,3800 r180 top
J8 "EN1_2" Samtec_HTSW-102-07-G-S 3650,3800 r180 top
J9 "EN2_2" Samtec_HTSW-102-07-G-S 3900,3800 r180 top
J10 "PGND" Johnson_108-0740-001 3005,475 r270 top
J11 "+VOUT" Johnson_108-0740-001 1150,475 r90 top
J12 "PGND" Johnson_108-0740-001 1900,475 r90 top
J13 "-VS" Johnson_108-0740-001 3750,475 r270 top
L1 "DRQ74-681-R" DRQ74 4500,3600 r180 top value=680uH
L2 "7443641500" FP-7443641500_SMT_IND_28MM0_19MM4-MFG 675,2935 r0 top locked value=15uH
L2A "Comment" 9R6UH_SMT_IND_22MM 675,2710 r0 top locked
L3 "VLBU1007090T-R33L" VLBU1007090 175,1050 r90 top value=330nH
L4 "VLBU1007090T-R33L" VLBU1007090 4925,650 r270 top value=330nH
L5 "7443641500" FP-7443641500_SMT_IND_28MM0_19MM4-MFG 1925,2935 r0 top locked value=15uH
L5A "Comment" 9R6UH_SMT_IND_22MM 1925,2710 r0 top locked
L6 "VLBU1007090T-R33L" VLBU1007090 1470,1000 r0 top value=330nH
L7 "7443641500" FP-7443641500_SMT_IND_28MM0_19MM4-MFG 3175,2935 r0 top locked value=15uH
L7A "Comment" 9R6UH_SMT_IND_22MM 3175,2710 r0 top locked
L8 "VLBU1007090T-R33L" VLBU1007090 2930,1000 r180 top value=330nH
L9 "7443641500" FP-7443641500_SMT_IND_28MM0_19MM4-MFG 4425,2935 r0 top locked value=15uH
L9A "Comment" 9R6UH_SMT_IND_22MM 4425,2710 r0 top locked
L10 "VLBU1007090T-R33L" VLBU1007090 3760,1000 r0 top value=330nH
LBL1 "Label" Label_1250x250 2505,2595 r180 bottom
Logo1 "FCC disclaimer" FCC_disclaimer_stacked 3105,3735 r0 top
LOGO2 "CAUTION HOT SURFACE" IEC_HotSurface_Small 480,1925 r0 top
LOGO3 "CAUTION HOT SURFACE" IEC_HotSurface_Small 4230,1925 r0 top
LOGO4 "DANGER HIGH VOLTAGE" IEC_HighVoltage_Small 2550,2355 r0 top
NT1 "Net-Tie" Net-Tie_10mil 1310,2940 r270 bottom net-tie
NT2 "Net-Tie" Net-Tie_10mil 3810,2940 r270 bottom net-tie
Q1 "MMBTA56LT1G" SOT-23L 4750,2685 r180 bottom value="80 V"
Q2 "2N7002E-T1-E3" SOT-23 4595,2690 r90 bottom value=60V
Q3 "MMBTA56LT1G" SOT-23L 2505,3150 r180 bottom value="80 V"
Q4 "MMBTA56LT1G" SOT-23L 2660,3150 r180 bottom value="80 V"
Q5 "2N7002E-T1-E3" SOT-23 1990,3275 r0 bottom value=60V
Q6 "2N7002E-T1-E3" SOT-23 1990,3425 r0 bottom value=60V
Q7 "2N7002E-T1-E3" SOT-23 950,3455 r270 bottom value=60V
Q8 "2N7002E-T1-E3" SOT-23 950,3605 r270 bottom value=60V
Q9 "2N7002E-T1-E3" SOT-23 3450,3455 r270 bottom value=60V
Q10 "2N7002E-T1-E3" SOT-23 3450,3605 r270 bottom value=60V
Q11 "BSC160N15NS5ATMA1" PG-TDSON-8 330,1650 r180 bottom value=150V
Q12 "BSC160N15NS5ATMA1" PG-TDSON-8 690,1650 r180 bottom value=150V
Q13 "BSC160N15NS5ATMA1" PG-TDSON-8 690,1960 r180 bottom value=150V
Q14 "BSC160N15NS5ATMA1" PG-TDSON-8 330,1960 r180 bottom value=150V
Q15 "BSC160N15NS5ATMA1" PG-TDSON-8 1580,1650 r180 bottom value=150V
Q16 "BSC160N15NS5ATMA1" PG-TDSON-8 1940,1650 r180 bottom value=150V
Q17 "BSC160N15NS5ATMA1" PG-TDSON-8 1940,1960 r180 bottom value=150V
Q18 "BSC160N15NS5ATMA1" PG-TDSON-8 1580,1960 r180 bottom value=150V
Q19 "BSC160N15NS5ATMA1" PG-TDSON-8 2830,1650 r180 bottom value=150V
Q20 "BSC160N15NS5ATMA1" PG-TDSON-8 3190,1650 r180 bottom value=150V
Q21 "BSC160N15NS5ATMA1" PG-TDSON-8 3190,1960 r180 bottom value=150V
Q22 "BSC160N15NS5ATMA1" PG-TDSON-8 2830,1960 r180 bottom value=150V
Q23 "BSC160N15NS5ATMA1" PG-TDSON-8 4080,1650 r180 bottom value=150V
Q24 "BSC160N15NS5ATMA1" PG-TDSON-8 4440,1650 r180 bottom value=150V
Q25 "BSC160N15NS5ATMA1" PG-TDSON-8 4440,1960 r180 bottom value=150V
Q26 "BSC160N15NS5ATMA1" PG-TDSON-8 4080,1960 r180 bottom value=150V
R1 "Resistor" 0603L 4880,2720 r0 bottom value=100k
R2 "Resistor" 0603L 4880,2645 r0 bottom value=100k
R3 "Resistor" 0603L 4715,2900 r90 bottom value=100k
R4 "Resistor" 0603L 4600,2900 r90 bottom value=560k
R5 "Resistor" 0603L 4735,3455 r0 bottom value=30k
R6 "Resistor" 0603L 4600,3325 r90 bottom value=143k
R7 "Resistor" 0603L 4595,2580 r0 bottom value=100k
R8 "Resistor" 0603L 4660,2900 r270 bottom value=4.53k
R9 "Resistor" 0603L 4600,3200 r90 bottom value=20.0k
R10 "Resistor" 0603L 1960,3140 r270 bottom value=10.0k
R11 "Resistor" 0603L 2350,3110 r0 bottom value=57.6k
R12 "Resistor" 0603L 2235,3110 r0 bottom value=100
R13 "Resistor" 0603L 2035,3140 r90 bottom value=100k
R14 "Resistor" 0603L 2615,3360 r90 bottom value=6.65k
R15 "Resistor" 0603L 2675,3360 r90 bottom value=100k
R16 "Resistor" 0603L 2555,3360 r90 bottom value=4.02k
R17 "Resistor" 0603L 2415,3275 r180 bottom value=24.0k
R18 "Resistor" 0603L 2495,2820 r180 bottom value=0
R19 "Resistor" 0603L 2820,3250 r180 bottom value=4.99k
R20 "Resistor" 0603L 2215,3345 r0 bottom value=10.0k
R21 "Resistor" 0603L 2340,3495 r180 bottom value=20.0k
R22 "Resistor" 0603L 2115,3370 r90 bottom value=10.0k
R23 "Resistor" 0603L 2215,3495 r0 bottom value=20.0
R24 "DNP" 0603L 2600,2820 r180 bottom value=0
R25 "Resistor" 0603L 2460,2950 r90 bottom value=8.66k
R26 "Resistor" 0603L 4980,3075 r90 bottom value=1.0Meg
R27 "Resistor" 0603L 4980,3185 r90 bottom value=100k
R28 "Resistor" 0603L 4925,3075 r270 bottom value=249k
R29 "Resistor" 0603L 940,2910 r0 bottom value=100k
R30 "Resistor" 0603L 940,2755 r180 bottom value=15.0k
R31 "Resistor" 0603L 1660,3005 r180 bottom value=100k
R32 "CRCW06033K24FKEA" 0603L 940,3345 r180 bottom value=3.24k
R33 "Resistor" 0603L 1295,3415 r90 bottom value=49.9k
R34 "Resistor" 0603L 1155,3415 r90 bottom value=49.9k
R35 "Resistor" 0603L 1225,3415 r90 bottom value=10.0k
R36 "Resistor" 0603L 825,3110 r90 bottom value=20.0k
R37 "Resistor" 0603L 775,3110 r270 bottom value=20.0k
R38 "Resistor" 0603L 1150,2485 r90 bottom value=2.0
R39 "Resistor" 0603L 1485,3415 r270 bottom value=15.0k
R40 "Resistor" 0603L 940,2960 r180 bottom value=49.9k
R41 "Resistor" 0603L 1435,3415 r270 bottom value=26.7k
R42 "CRCW060324R9FKEA" 0603L 800,2960 r0 bottom value=24.9
R43 "Resistor" 0603L 1450,2485 r90 bottom value=2.0
R44 "Resistor" 0603L 940,3010 r0 bottom value=40.2k
R45 "CRCW06033K24FKEA" 0603L 1660,3345 r180 bottom value=3.24k
R46 "Resistor" 0603L 1660,2855 r180 bottom value=42.2k
R47 "Resistor" 0603L 995,2705 r0 bottom value=18.7k
R48 "Resistor" 0603L 1660,2805 r180 bottom value=15.0k
R49 "Resistor" 0603L 3440,2910 r0 bottom value=100k
R50 "Resistor" 0603L 3440,2755 r180 bottom value=15.0k
R51 "Resistor" 0603L 4160,3005 r180 bottom value=100k
R52 "CRCW06033K24FKEA" 0603L 3440,3345 r180 bottom value=3.24k
R53 "Resistor" 0603L 3795,3415 r90 bottom value=49.9k
R54 "Resistor" 0603L 3655,3415 r90 bottom value=49.9k
R55 "Resistor" 0603L 3725,3415 r90 bottom value=10.0k
R56 "Resistor" 0603L 3325,3110 r90 bottom value=20.0k
R57 "Resistor" 0603L 3275,3110 r270 bottom value=20.0k
R58 "Resistor" 0603L 3650,2485 r90 bottom value=2.0
R59 "Resistor" 0603L 3985,3415 r270 bottom value=15.0k
R60 "Resistor" 0603L 3440,2960 r180 bottom value=49.9k
R61 "Resistor" 0603L 3935,3415 r270 bottom value=26.7k
R62 "CRCW060324R9FKEA" 0603L 3300,2960 r0 bottom value=24.9
R63 "Resistor" 0603L 3950,2485 r90 bottom value=2.0
R64 "Resistor" 0603L 3440,3010 r0 bottom value=40.2k
R65 "CRCW06033K24FKEA" 0603L 4160,3345 r180 bottom value=3.24k
R66 "Resistor" 0603L 4160,2905 r180 bottom value=42.2k
R67 "Resistor" 0603L 3495,2700 r0 bottom value=18.7k
R68 "Resistor" 0603L 4160,2805 r180 bottom value=15.0k
R69 "Resistor" 2010 105,2100 r90 bottom value=10
R70 "Resistor_Kelvin" RES_WSL2726 1170,2060 r270 top value=0.001
R71 "Resistor" 0603L 510,1600 r270 bottom value=49.9k
R72 "Resistor" 0603L 480,1495 r0 bottom value=0
R73 "Resistor" 0603L 870,1600 r90 bottom value=49.9k
R74 "Resistor" 0603L 870,1910 r90 bottom value=49.9k
R75 "Resistor" 2010 915,2100 r90 bottom value=10
R76 "Resistor" 0603L 940,3245 r180 bottom value=2.0
R77 "Resistor" 0603L 940,3195 r180 bottom value=2.0
R78 "Resistor" 0603L 840,1495 r0 bottom value=0
R79 "Resistor" 0603L 840,1805 r0 bottom value=0
R80 "Resistor" 0603L 510,1910 r270 bottom value=49.9k
R81 "Resistor" 0603L 480,1805 r0 bottom value=0
R82 "Resistor" 2010 1205,1340 r0 bottom value=0.5
R83 "Resistor" 2010 1205,1705 r0 bottom value=0.5
R84 "Resistor" 2010 1355,2100 r90 bottom value=10
R85 "Resistor" 2010 2455,1340 r0 bottom value=0.5
R86 "Resistor" 2010 2455,1705 r0 bottom value=0.5
R87 "Resistor_Kelvin" RES_WSL2726 2420,2060 r270 top value=0.001
R88 "Resistor" 0603L 1760,1600 r90 bottom value=49.9k
R89 "Resistor" 0603L 1730,1495 r0 bottom value=0
R90 "Resistor" 0603L 1660,3245 r0 bottom value=2.0
R91 "Resistor" 0603L 1660,3195 r0 bottom value=2.0
R92 "Resistor" 0603L 2120,1600 r90 bottom value=49.9k
R93 "Resistor" 0603L 2120,1910 r90 bottom value=49.9k
R94 "Resistor" 2010 2165,2100 r90 bottom value=10
R95 "Resistor" 0603L 2090,1495 r0 bottom value=0
R96 "Resistor" 0603L 2090,1805 r0 bottom value=0
R97 "Resistor" 0603L 1760,1910 r90 bottom value=49.9k
R98 "Resistor" 0603L 1730,1805 r0 bottom value=0
R99 "Resistor" 2010 2605,2100 r90 bottom value=10
R100 "Resistor_Kelvin" RES_WSL2726 3670,2060 r270 top value=0.001
R101 "Resistor" 0603L 3010,1600 r270 bottom value=49.9k
R102 "Resistor" 0603L 2980,1495 r0 bottom value=0
R103 "Resistor" 0603L 3370,1600 r90 bottom value=49.9k
R104 "Resistor" 0603L 3370,1910 r90 bottom value=49.9k
R105 "Resistor" 2010 3415,2100 r90 bottom value=10
R106 "Resistor" 0603L 3440,3245 r180 bottom value=2.0
R107 "Resistor" 0603L 3440,3195 r180 bottom value=2.0
R108 "Resistor" 0603L 3340,1495 r0 bottom value=0
R109 "Resistor" 0603L 3340,1805 r0 bottom value=0
R110 "Resistor" 0603L 3010,1910 r270 bottom value=49.9k
R111 "Resistor" 0603L 2980,1805 r0 bottom value=0
R112 "Resistor" 2010 3700,1340 r0 bottom value=0.5
R113 "Resistor" 2010 3700,1705 r0 bottom value=0.5
R114 "Resistor" 2010 3855,2100 r90 bottom value=10
R115 "Resistor" 2010 4900,1340 r0 bottom value=0.5
R116 "Resistor" 2010 4900,1705 r0 bottom value=0.5
R117 "Resistor_Kelvin" RES_WSL2726 4920,2060 r270 top value=0.001
R118 "Resistor" 0603L 4260,1600 r90 bottom value=49.9k
R119 "Resistor" 0603L 4230,1495 r0 bottom value=0
R120 "Resistor" 0603L 4160,3245 r0 bottom value=2.0
R121 "Resistor" 0603L 4160,3195 r0 bottom value=2.0
R122 "Resistor" 0603L 4620,1600 r90 bottom value=49.9k
R123 "Resistor" 0603L 4620,1910 r90 bottom value=49.9k
R124 "Resistor" 2010 4665,2100 r90 bottom value=10
R125 "Resistor" 0603L 4590,1495 r0 bottom value=0
R126 "Resistor" 0603L 4590,1805 r0 bottom value=0
R127 "Resistor" 0603L 4260,1910 r90 bottom value=49.9k
R128 "Resistor" 0603L 4230,1805 r0 bottom value=0
T1 "CB70-14-CY" Panduit_CXS70-14-C 3000,475 r90 top
T2 "CB70-14-CY" Panduit_CXS70-14-C 1150,475 r90 top
T3 "CB70-14-CY" Panduit_CXS70-14-C 1900,475 r90 top
T4 "CB70-14-CY" Panduit_CXS70-14-C 3750,470 r90 top
TP1 "AGND" Keystone1598-2 1650,3550 r0 top
TP2 "AGND" Keystone1598-2 4150,3550 r0 top
TP3 "SW1_1" Testpoint_Keystone_Miniature 500,2190 r180 bottom
TP4 "-VIN" Testpoint_Keystone_Miniature 955,1690 r90 bottom
TP5 "PGND" Keystone5011 2600,100 r0 top
TP6 "+VOUT" Keystone5010 750,100 r0 top
TP7 "PGND" Keystone5011 2300,100 r0 top
TP8 "-VS" Keystone5012 4150,100 r0 top
TP9 "SW2_1" Testpoint_Keystone_Miniature 1750,2190 r180 bottom
TP10 "-VIN" Testpoint_Keystone_Miniature 2205,1690 r270 bottom
TP11 "SW1_2" Testpoint_Keystone_Miniature 3000,2190 r180 bottom
TP12 "-VIN" Testpoint_Keystone_Miniature 3455,1690 r90 bottom
TP13 "SW2-2" Testpoint_Keystone_Miniature 4250,2190 r180 bottom
TP14 "-VIN" Testpoint_Keystone_Miniature 4705,1690 r90 bottom
U1 "LM5017" DDA0008B_L 4750,3125 r90 bottom
U2 "TPS70960" DBV0005A_N 3075,3300 r270 bottom
U3 "LM8261M5/NOPB" DBV0005A_N 2370,3385 r0 bottom
U4 "TLV7021DCKR" DCK0005A_N 2550,2925 r90 bottom
U5 "LM4040-NDBZ" DBZ0003A_N 2840,3370 r0 bottom
U6 "CMP-0013575-3" PHP0048D_L 1300,3070 r180 bottom
U7 "UCC21225ANPL" NPL0013A 1300,2425 r270 bottom
U8 "CMP-0013575-3" PHP0048D_L 3800,3070 r180 bottom
U9 "UCC21225ANPL" NPL0013A 3800,2425 r270 bottom
ZZ1 "This Assembly Note is for PCB labels only" AssemblyNoteLabel 160,4375 r0 top
ZZ2 "These assemblies are ESD sensitive, ESD precautions shall be observed." AssemblyNote 160,4284.11 r0 top
ZZ3 "These assemblies must be clean and free from flux and all contaminants. Use of no clean flux is not acceptable." AssemblyNote 160,4195.56 r0 top
ZZ4 "These assemblies must comply with workmanship standards IPC-A-610 Class 2, unless otherwise specified." AssemblyNote 160,4107 r0 top

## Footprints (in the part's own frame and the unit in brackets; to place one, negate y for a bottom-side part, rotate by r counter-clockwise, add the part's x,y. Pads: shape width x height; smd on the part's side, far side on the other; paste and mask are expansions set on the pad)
9R6UH_SMT_IND_22MM [mm]
  rect 5.3x7.5 smd paste+0 mask+0: 1(-6.95,-7.75) 2(6.95,-7.75)
  rect 6.8x6.8 smd paste+0 mask+0: 3(0,8.1)
0603L [mm] "0603 from SM-752 data"
  rect 0.8x0.85 smd: 1(-0.7,0) 2(0.7,0)
  silkscreen extent -0.07,-0.33 0.07,0.33, body extent -0.87,-0.47 0.87,0.47, height 1
0805_HV [mil] "0805 with 30mil clearance between pads"
  rect 50x63 smd: 1(-40,0) 2(40,0)
  silkscreen extent -74,-40 74,40, body extent -43,-29 43,29, height 57
0805L [mm] "0805 from SM-752 data"
  rect 1.1x1.4 smd: 1(-0.75,0) 2(0.75,0)
  body extent -1.1,-0.72 1.1,0.72, height 1.45
1210_180L [mm] "1210"
  rect 1.1x2.6 smd: 1(-1.35,0) 2(1.35,0)
  silkscreen extent -0.4,-1.2 0.4,1.2, body extent -1.7,-1.35 1.7,1.35, height 1.8
1210_220L [mm] "1210"
  rect 1.1x2.6 smd: 1(-1.35,0) 2(1.35,0)
  silkscreen extent -0.4,-1.2 0.4,1.2, body extent -1.7,-1.35 1.7,1.35, height 2.2
2010 [mm] "Chip Capacitor, Body 5.08x2.54mm, IPC Medium Density"
  rect 1.6x2.7 smd: 1(-2.3,0) 2(2.3,0)
  silkscreen extent -3.42,-1.65 3.42,1.65, body extent -2.73,-1.45 2.73,1.45, height 1.66
AssemblyNote [mil] "Assembly Note"
AssemblyNoteLabel [mil] "Assembly Note for PCB Labels"
CAPSMT_62_LH0 [mm] "16 x 16.5mm:  Chemi-Con LH0"
  rect 7.8x9.6 smd: 1(-6.25,0) 2(6.25,0)
  silkscreen extent -8.55,-8.55 8.55,8.55, body extent -8.55,-8.55 8.55,8.55, height 17
CR_800x1200 [mm] "SMD, 2-Leads, Dia 8mm"
  rect 3.5x2 smd: 1(-3.25,0) 2(3.25,0)
  silkscreen extent -6.4,-4.25 4.25,4.25, body extent -4.25,-4.25 4.25,4.25, height 12.11
CR_1000x1270 [mm] "SMD, 2-Leads, Dia 10.5mm, Pin Spacing 8mm"
  rect 4x2 smd: 1(-4,0) 2(4,0)
  silkscreen extent -7.4,-5.25 5.25,5.25, body extent -5.25,-5.25 5.25,5.25, height 12.71
DBV0005A_N [mm] "SOT23, 5-Leads, Body 2.9x1.6mm, Pitch 0.95mm, Lead Span 2.8mm, IPC Medium Density"
  rrect17% 1x0.6 smd: 1(-1.375,0.95) 2(-1.375,0) 3(-1.375,-0.95) 4(1.375,-0.95) 5(1.375,0.95)
  silkscreen extent -0.25,-1.55 0.25,1.55, body extent -1.42,-1.46 1.42,1.46, height 1.09
DBZ0003A_N [mm] "SOT23, 3-Leads, Body 2.9x1.3mm, Pitch 0.95mm, Lead Span 2.4mm, IPC Medium Density"
  rrect17% 1x0.6 smd: 1(-1.2,0.95) 2(-1.2,-0.95) 3(1.2,0)
  silkscreen extent 0.2,-1.5 0.7,1.5, body extent -1.26,-1.46 1.26,1.46, height 0.98
DCK0005A_N [mm] "SOT353, 5-Leads, Body 2x1.3mm, Pitch 0.65mm, Lead Span 2.1mm, IPC Medium Density"
  rrect25% 0.85x0.4 smd: 1(-1.125,0.65) 2(-1.125,0) 3(-1.125,-0.65) 4(1.125,-0.65) 5(1.125,0.65)
  silkscreen extent -1.48,-1.02 0.55,1.1, body extent -1.14,-1 1.14,1, height 0.95
DDA0008B_L [mm] "SOIC, 8-Leads, Body 4.9x3.9mm, Pitch 1.27mm, Exposed Pad, IPC High Density"
  rrect18% 1.25x0.55 smd: 1(-2.625,1.905) 2(-2.625,0.635) 3(-2.625,-0.635) 4(-2.625,-1.905) 5(2.625,-1.905) 6(2.625,-0.635) 7(2.625,0.635) 8(2.625,1.905)
  rrect7% 2.95x4.9 smd paste-1.5 mask-1.5: 9(0,0)
  rrect4% 2.71x3.4 on Bottom Paste: 9(0,0)
  rrect4% 2.71x3.4 on Bottom Solder: 9(0,0)
  silkscreen extent -3,-2.5 1.1,2.5, body extent -3.01,-2.45 3.01,2.45, height 1.57
DRQ74 [mm] "COILTRONICS"
  rect 1.73x1 smd: 1(-3.085,0.7) 2(-3.085,-0.7) 3(3.085,-0.7) 4(3.085,0.7)
  silkscreen extent -4.48,-3.8 3.8,3.8, body extent -3.8,-3.8 3.8,3.8, height 4.46
FCC_disclaimer_stacked [mil]
Fiducial10-20 [mm]
  round 1 smd mask+0.5: 1(0,0)
  Top Layer keep-out circle w1.178: c0,0 r0.5
FP-7443641500_SMT_IND_28MM0_19MM4-MFG [mm]
  rect 5.33x5.59 smd paste+0 mask+0: 1(-5.075,-14.355) 2(5.075,-14.355)
  rect 6.35x5.28 smd paste+0 mask+0: 3(0,7.72)
  body extent -14.1,-17.25 14.1,10.46, height 0.25
IEC_HighVoltage_Small [mil]
  silkscreen extent -107,-88 107,97
IEC_HotSurface_Small [mil]
  silkscreen extent -107,-93 107,92
Johnson_108-0740-001 [mm] "Banana Jack Uninsulated Standard Type"
  round 12 hole 6.858: 1(0,0)
  body extent -4.77,-5.43 4.75,5.57, height 2.39
Keystone1598-2 [mm] "Triple Turret"
  round 3.5 hole 2.5: 1(0,0)
  silkscreen extent -2.08,-2.08 2.08,2.08, body extent -1.6,-1.6 1.59,1.6, height 7.72
Keystone5010 [mil] "Keystone Multipurpose loops"
  round 87 hole 63: 1(0,0)
  silkscreen extent -70,-70 70,70, body extent -63,-63 63,62, height 319
Keystone5011 [mil] "Keystone Multipurpose loops"
  round 87 hole 63: 1(0,0)
  silkscreen extent -70,-70 70,70, body extent -63,-63 63,62, height 319
Keystone5012 [mil] "Keystone Multipurpose loops"
  round 87 hole 63: 1(0,0)
  silkscreen extent -70,-70 70,70, body extent -63,-63 63,62, height 319
KEYSTONE_2205 [mil] "THREAD HEX ALUMINUM STANDOFF 4-40, F-F 1\""
  round 1 on Mech4: 0(0,0)
  body extent -148,-128 148,128, height 1001
Label_1250x250 [mil] "Thermal Transfer Labels"
  round 1 on Mech14: 0(0,0)
  silkscreen extent -625,-125 625,125, body extent -625,-125 625,125, height 1
Net-Tie_10mil [mil] "10mil net tie, no solder mask opening, no solder paste"
  rect 10x10 smd paste-5 mask-5: 1(-10,0) 2(10,0)
  Top Layer region: -6,5 6,5 6,-5 -6,-5
NPL0013A [mm] "SMD, 13-Leads, Body 5x5mm, Pitch 0.65mm"
  rrect33% 0.65x0.3 smd: 1(-2.075,1.95) 2(-2.075,1.3) 3(-2.075,0.65) 4(-2.075,0) 5(-2.075,-0.65) 6(-2.075,-1.3) 7(-2.075,-1.95) 8(2.075,-1.95) 9(2.075,-1.3) 10(2.075,-0.65) 11(2.075,0.65) 12(2.075,1.3) 13(2.075,1.95)
  silkscreen extent -2.5,-2.65 2.5,2.65, body extent -2.5,-2.5 2.5,2.5, height 0.91
"NY PMS 440 0025 PH" [mm] "4-40 nylon screw and mounting hole"
  round 8 hole 3.2: 1(0,0)
  body extent -3.3,-3.3 3.3,3.3, height 2.69
Panduit_CXS70-14-C [mil] "Panduit"
  rect 770x500 hole 254 copper offset -74.8,0 paste-250: 1(0,0)
  body extent -960,-250 310,250, height 684
PG-TDSON-8 [mm] "Infineon recommended land pattern"
  rect 1.2x0.65 smd: 1(-2.825,1.905) 2(-2.825,0.635) 3(-2.825,-0.635) 4(-2.825,-1.905)
  rect 0.5x0.7 smd: 5(3.175,-2) 6(3.175,-0.675) 7(3.175,0.675) 8(3.175,2)
  rect 4.5x4.7 smd paste-2.25: 9(0.675,0)
  silkscreen extent -3.74,-3 3.74,3, body extent -3.18,-2.89 3.18,2.9, height 1.1
PHP0048D_L [mm] "Thin QFP, 48-Leads, Body 7x7mm, Pitch 0.5mm, Thermal Pad 4.5x4.5mm, IPC High Density"
  rrect100% 1.25x0.3 smd: 1(-4.125,2.75) 2(-4.125,2.25) 3(-4.125,1.75) 4(-4.125,1.25) 5(-4.125,0.75) 6(-4.125,0.25) 7(-4.125,-0.25) 8(-4.125,-0.75) 9(-4.125,-1.25) 10(-4.125,-1.75) 11(-4.125,-2.25) 12(-4.125,-2.75) 25(4.125,-2.75) 26(4.125,-2.25) 27(4.125,-1.75) 28(4.125,-1.25) 29(4.125,-0.75) 30(4.125,-0.25) 31(4.125,0.25) 32(4.125,0.75) 33(4.125,1.25) 34(4.125,1.75) 35(4.125,2.25) 36(4.125,2.75)
  rrect100% 0.3x1.25 smd: 13(-2.75,-4.125) 14(-2.25,-4.125) 15(-1.75,-4.125) 16(-1.25,-4.125) 17(-0.75,-4.125) 18(-0.25,-4.125) 19(0.25,-4.125) 20(0.75,-4.125) 21(1.25,-4.125) 22(1.75,-4.125) 23(2.25,-4.125) 24(2.75,-4.125) 37(2.75,4.125) 38(2.25,4.125) 39(1.75,4.125) 40(1.25,4.125) 41(0.75,4.125) 42(0.25,4.125) 43(-0.25,4.125) 44(-0.75,4.125) 45(-1.25,4.125) 46(-1.75,4.125) 47(-2.25,4.125) 48(-2.75,4.125)
  rrect2% 4.9x4.9 smd: 49(0,0)
  silkscreen extent -4.15,3.3 -3.9,3.55, body extent -4.51,-4.51 4.51,4.51, height 1.2
PowerDI123 [mm] "Diodes Inc recommended land pattern, document number DS30628 Rev. 6-2"
  rect 2.2x1.4 smd: 1(-1.275,0)
  rect 0.9x1.4 smd: 2(1.275,0)
  silkscreen extent -3.1,-1.09 1.76,1.09, body extent -2.37,-0.96 1.53,0.97, height 1
RES_WSL2726 [mm] "Vishay Dale"
  rect 2.44x5.6 smd: 1(-2.48,-2.07) 2(2.48,-2.065)
  rect 2.44x0.89 smd: 3(-2.48,2.065) 4(2.48,2.07)
  body extent -3.55,-4.45 3.55,2.45, height 3.22
Samtec_HTSW-102-07-G-S [mm] "Samtec 100mil, 1x2, 230 mil above insulator"
  rrect6% 1.65x1.65 hole 1.016: 1(-1.27,0)
  round 1.65 hole 1.016: 2(1.27,0)
  silkscreen extent -3.3,-1.27 2.54,1.27, body extent -2.54,-1.27 2.54,1.27, height 8.38
SOD-523 [mm] "NXP Semiconductor recommended land pattern, nominal STEP model"
  rect 0.8x0.6 smd paste-0.05: 1(-0.55,0) 2(0.55,0)
  silkscreen extent -1.65,-0.66 1.2,0.66, body extent -0.8,-0.4 0.8,0.4, height 0.72
SOT-23 [mm] "SOT23, 3-Leads, Body 2.9x1.3mm, Pitch 0.95mm, Lead Span 2.5mm, IPC Medium Density"
  rrect50% 1x0.6 smd: 1(-1.2,0.95) 2(-1.2,-0.95) 3(1.2,0)
  silkscreen extent -1.62,-1.5 0.7,1.5, body extent -1.16,-1.45 1.21,1.45, height 1
SOT-23L [mm] "SOT23, 3-Leads, Body 2.9x1.3mm, Pitch 0.95mm, Lead Span 2.5mm, IPC High Density"
  rrect50% 0.8x0.6 smd: 1(-1.1,0.95) 2(-1.1,-0.95) 3(1.1,0)
  silkscreen extent -1.5,-1.5 0.7,1.5, body extent -1.16,-1.45 1.21,1.45, height 1
Testpoint_Keystone_Miniature [mil] "Miniature SMT test point"
  rect 135x70 smd: 1(0,0)
  silkscreen extent -78,-46 78,45, body extent -52,-20 52,20, height 61
VLBU1007090 [mm] "SMD, 2-Leads, Body 7x10mm"
  rrect3% 3.2x3 smd: 1(-3.9,0) 2(3.9,0)
  body extent -5,-3.5 5,3.5, height 9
